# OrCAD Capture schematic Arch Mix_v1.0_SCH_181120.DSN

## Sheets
1 05 MCU PinOut: size A3; rev: v1.0
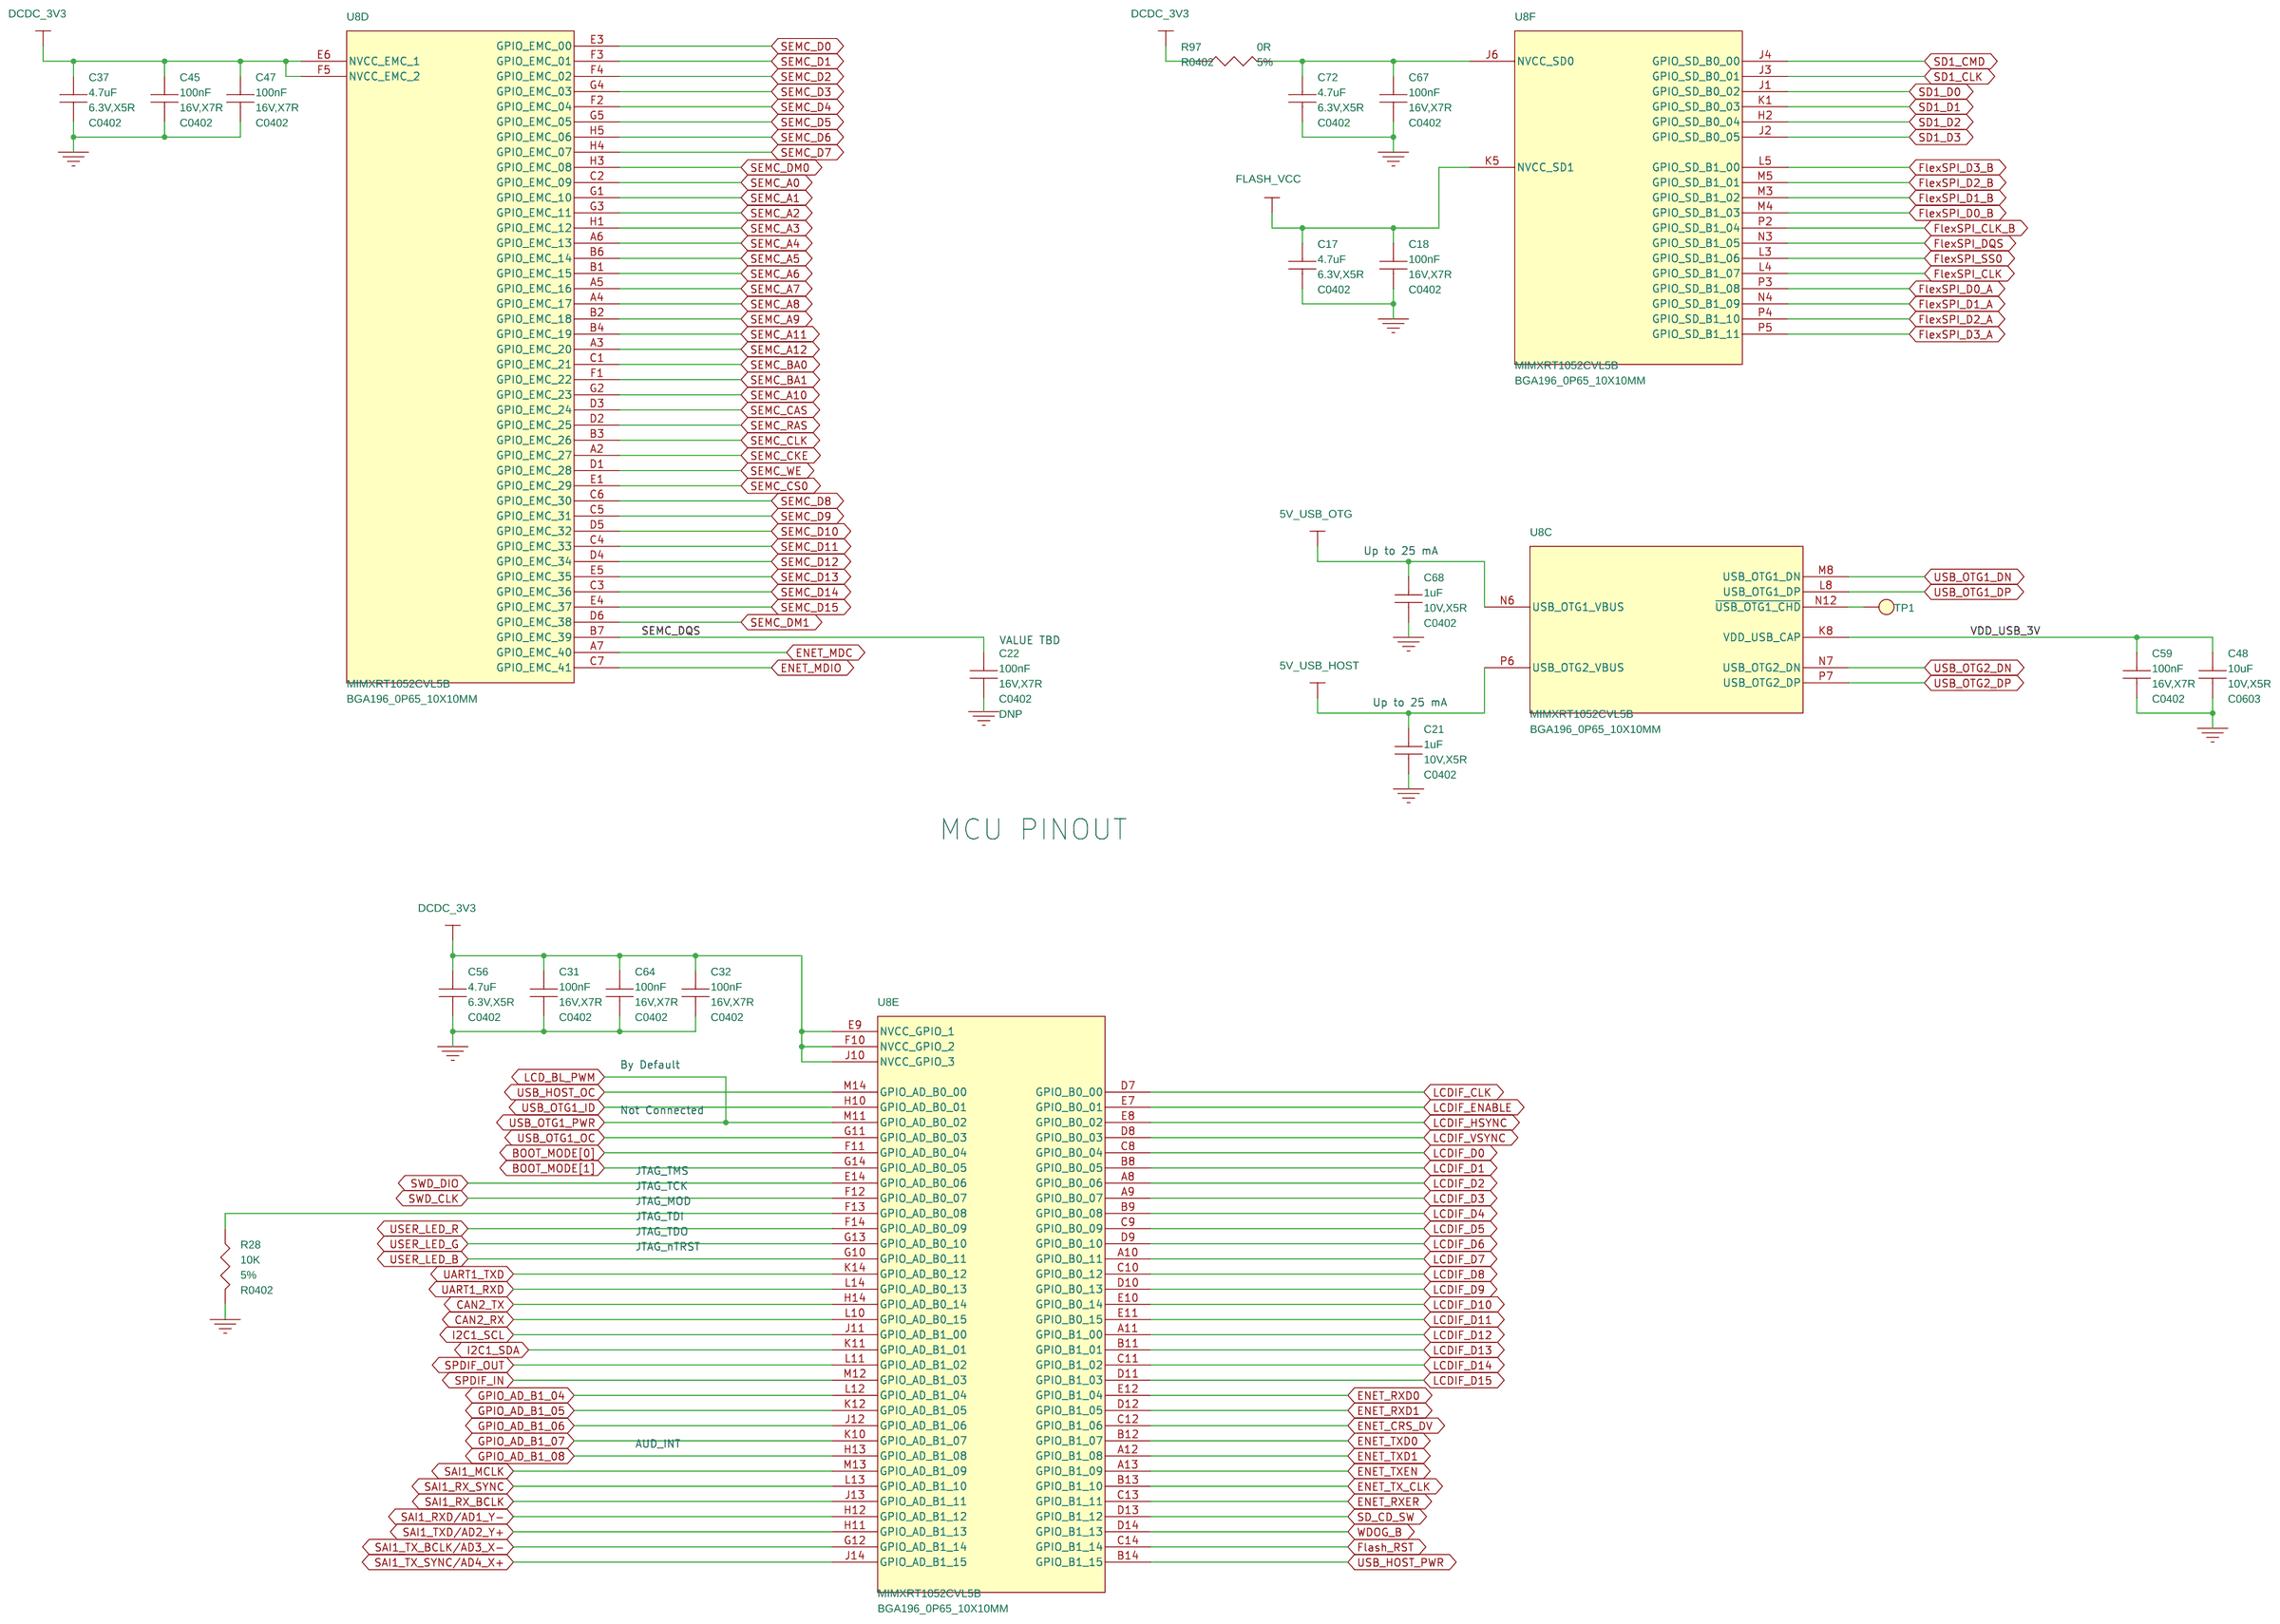
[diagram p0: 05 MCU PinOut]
2 03 Main Power: size A3
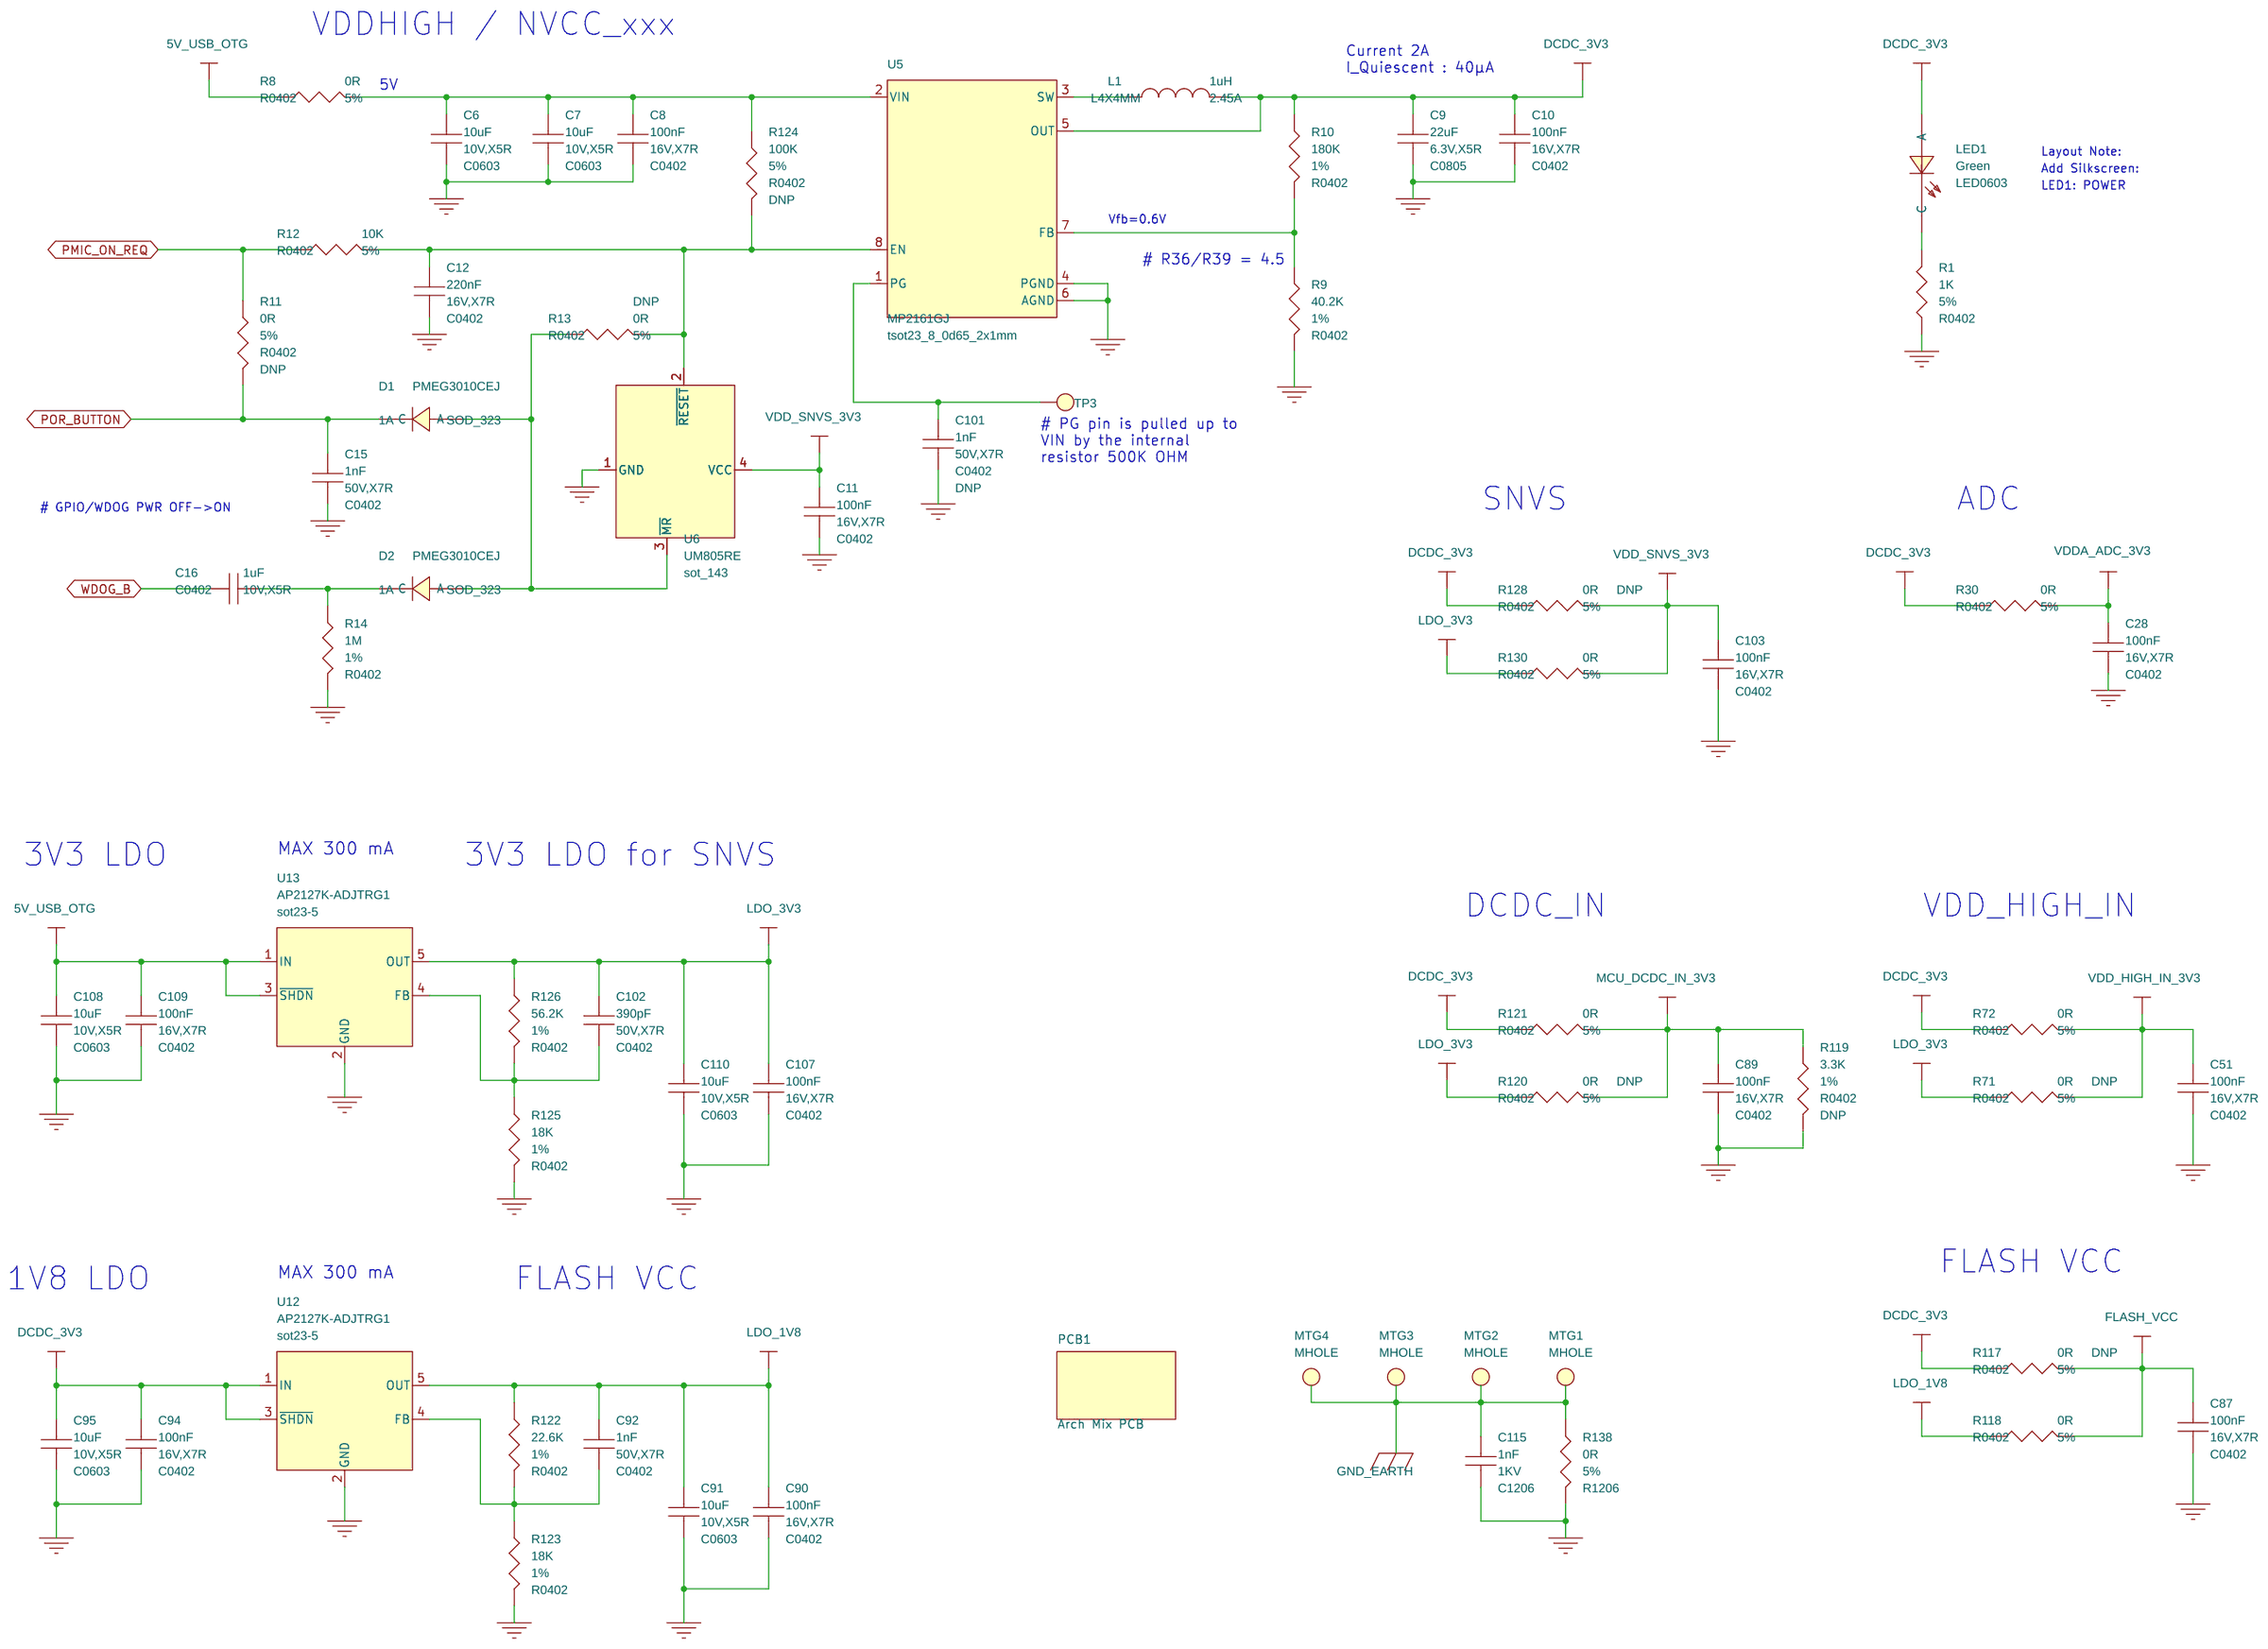
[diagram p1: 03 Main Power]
3 04 MCU Power: size A3
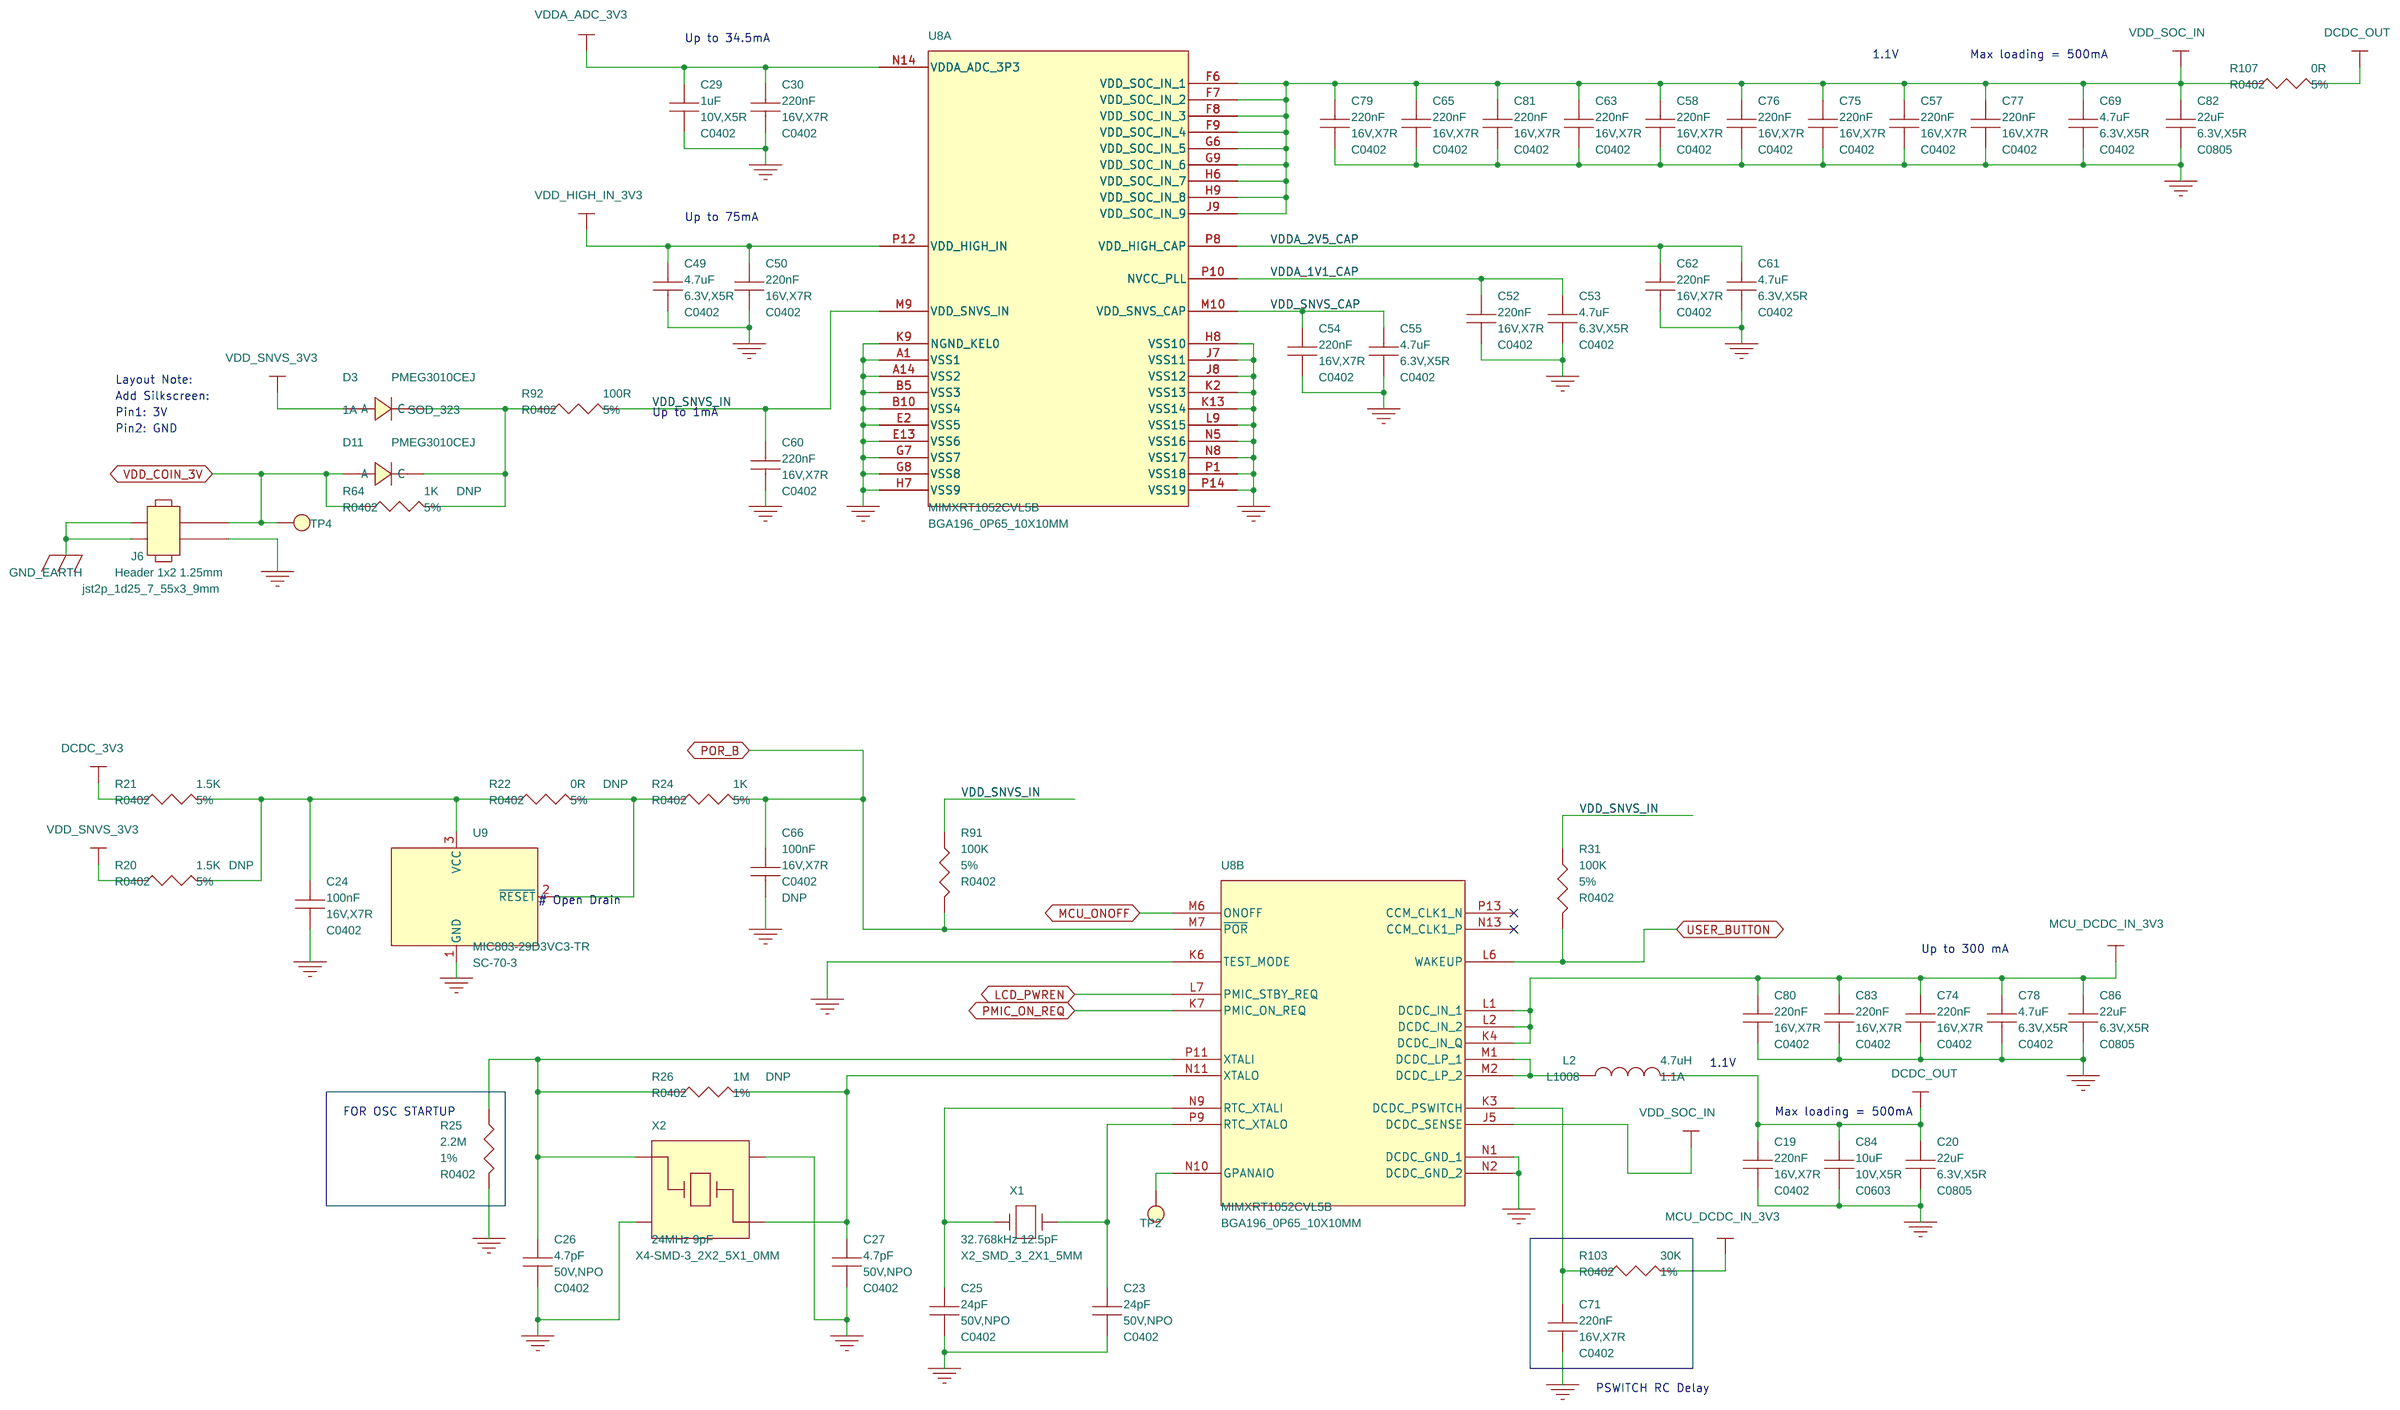
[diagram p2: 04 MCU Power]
4 02 Block Diagram
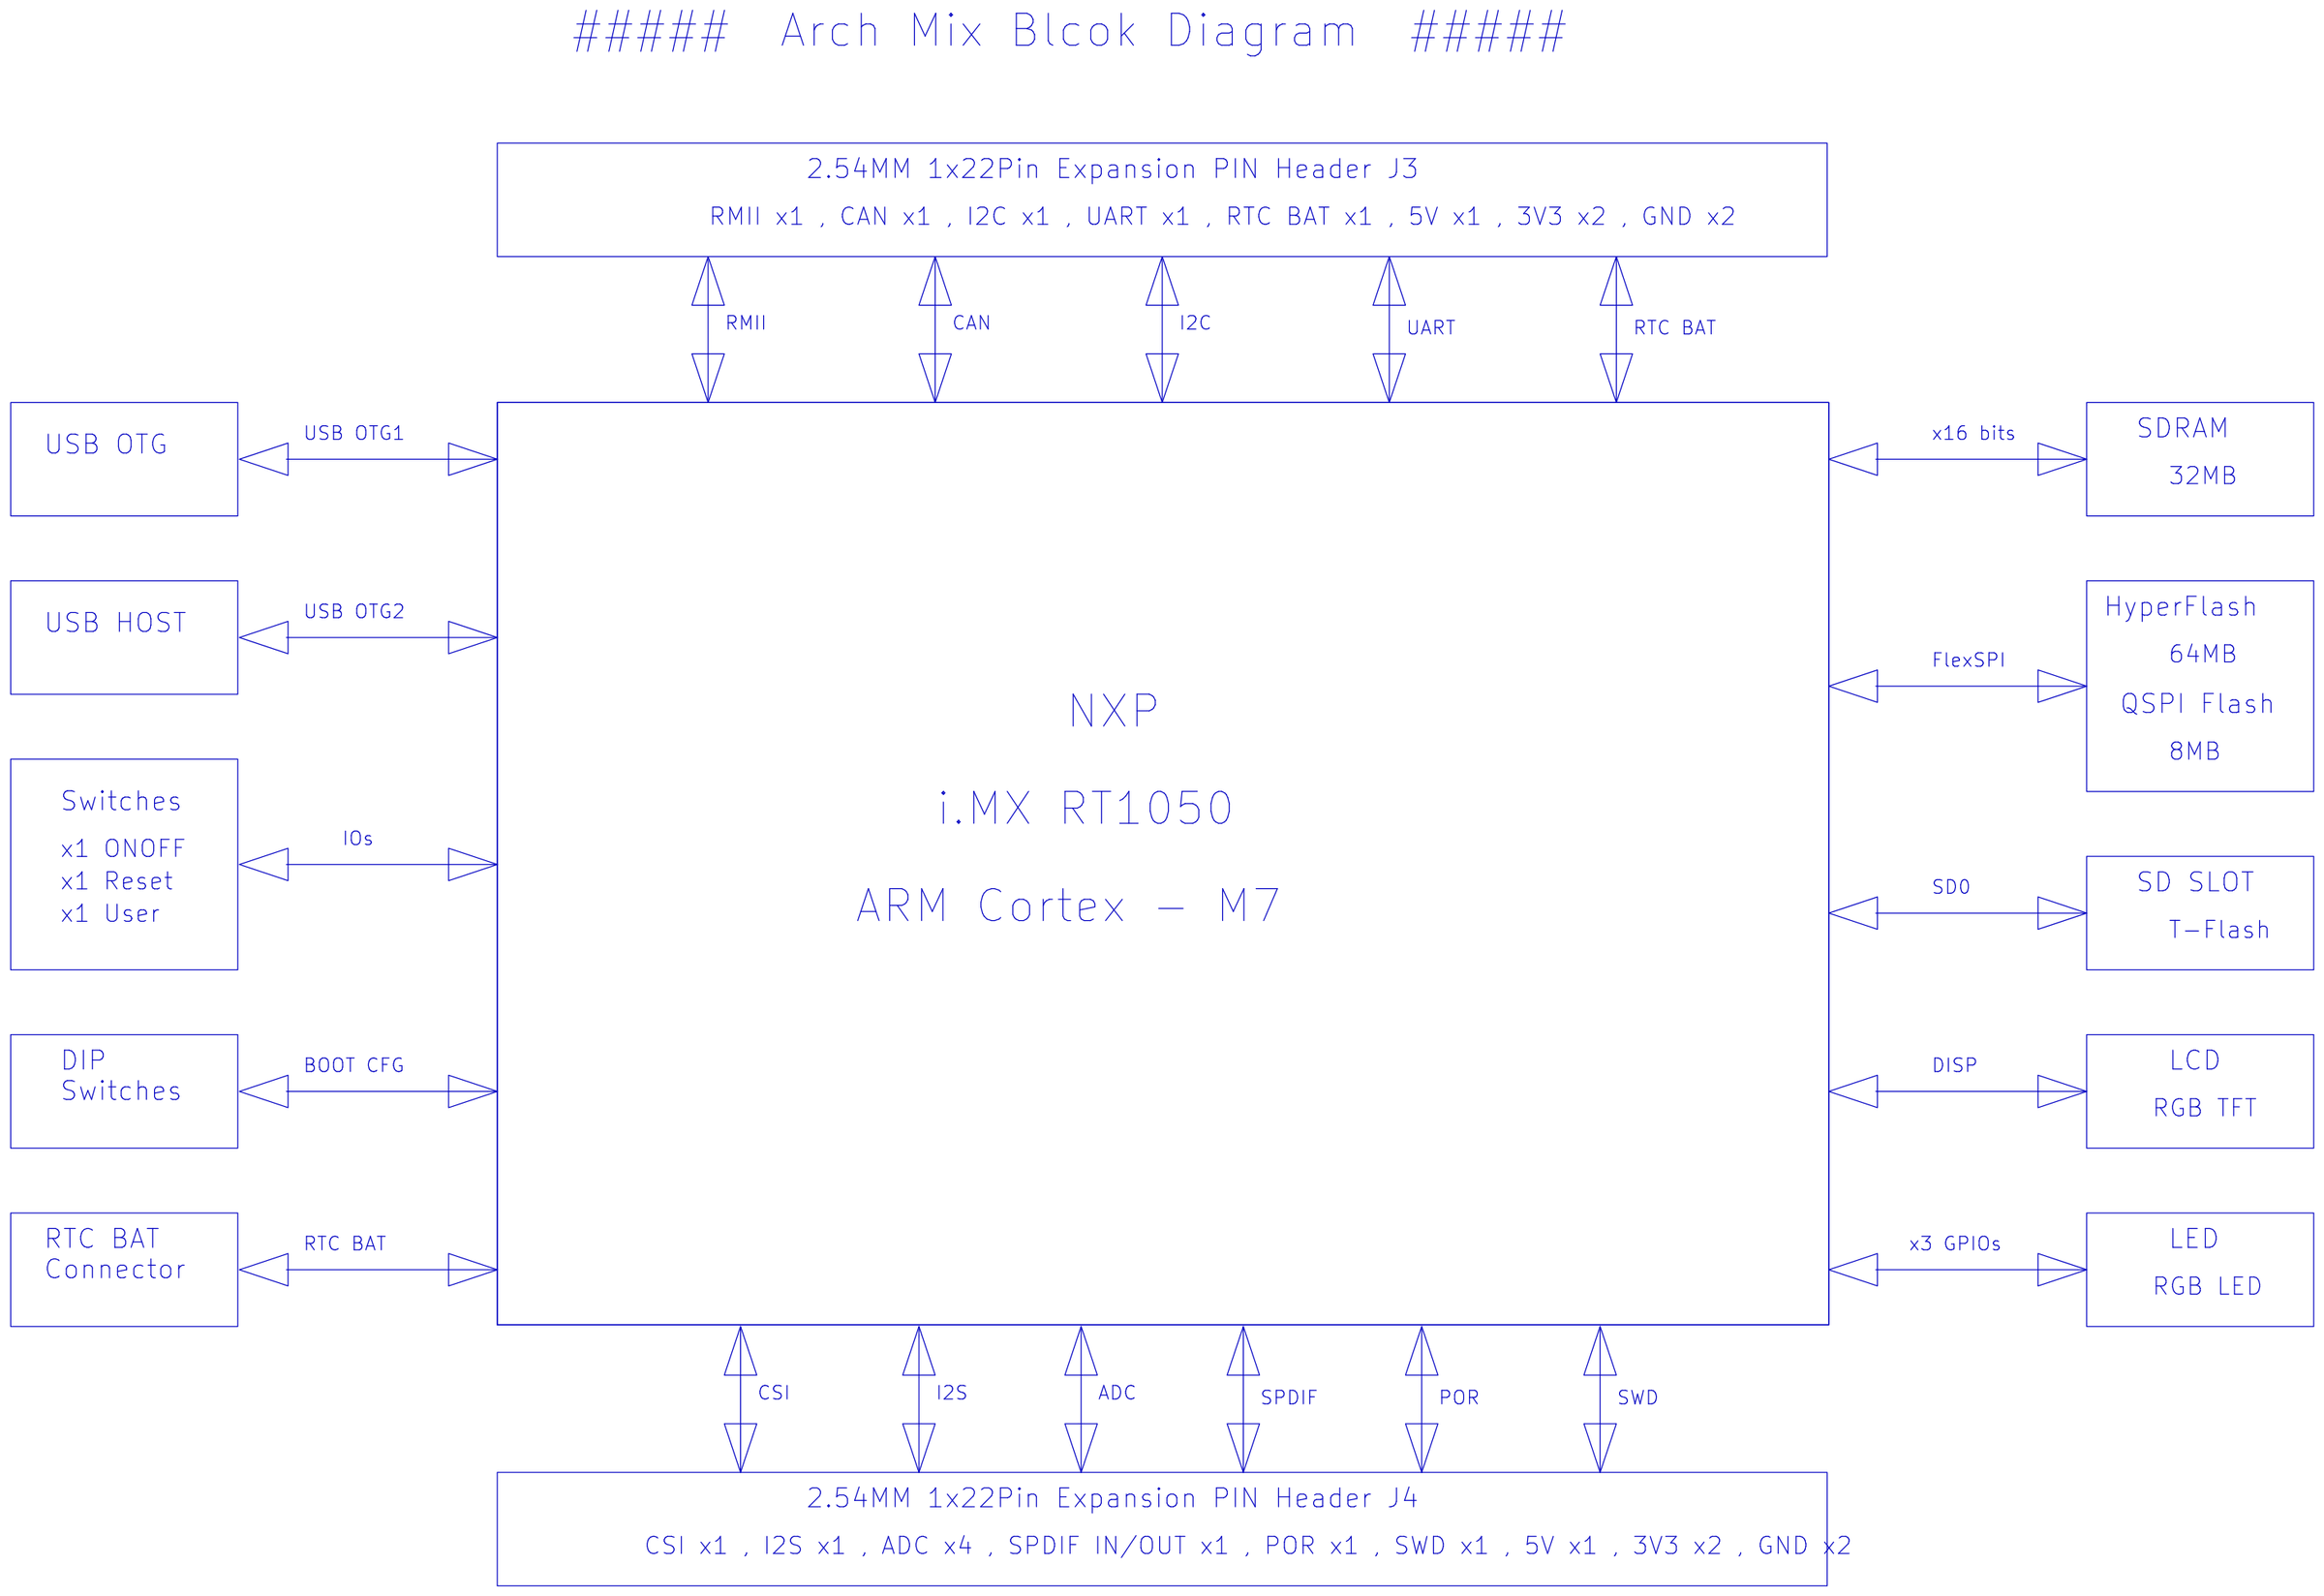
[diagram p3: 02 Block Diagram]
5 06 SDRAM / Flash / SD Card: size A3
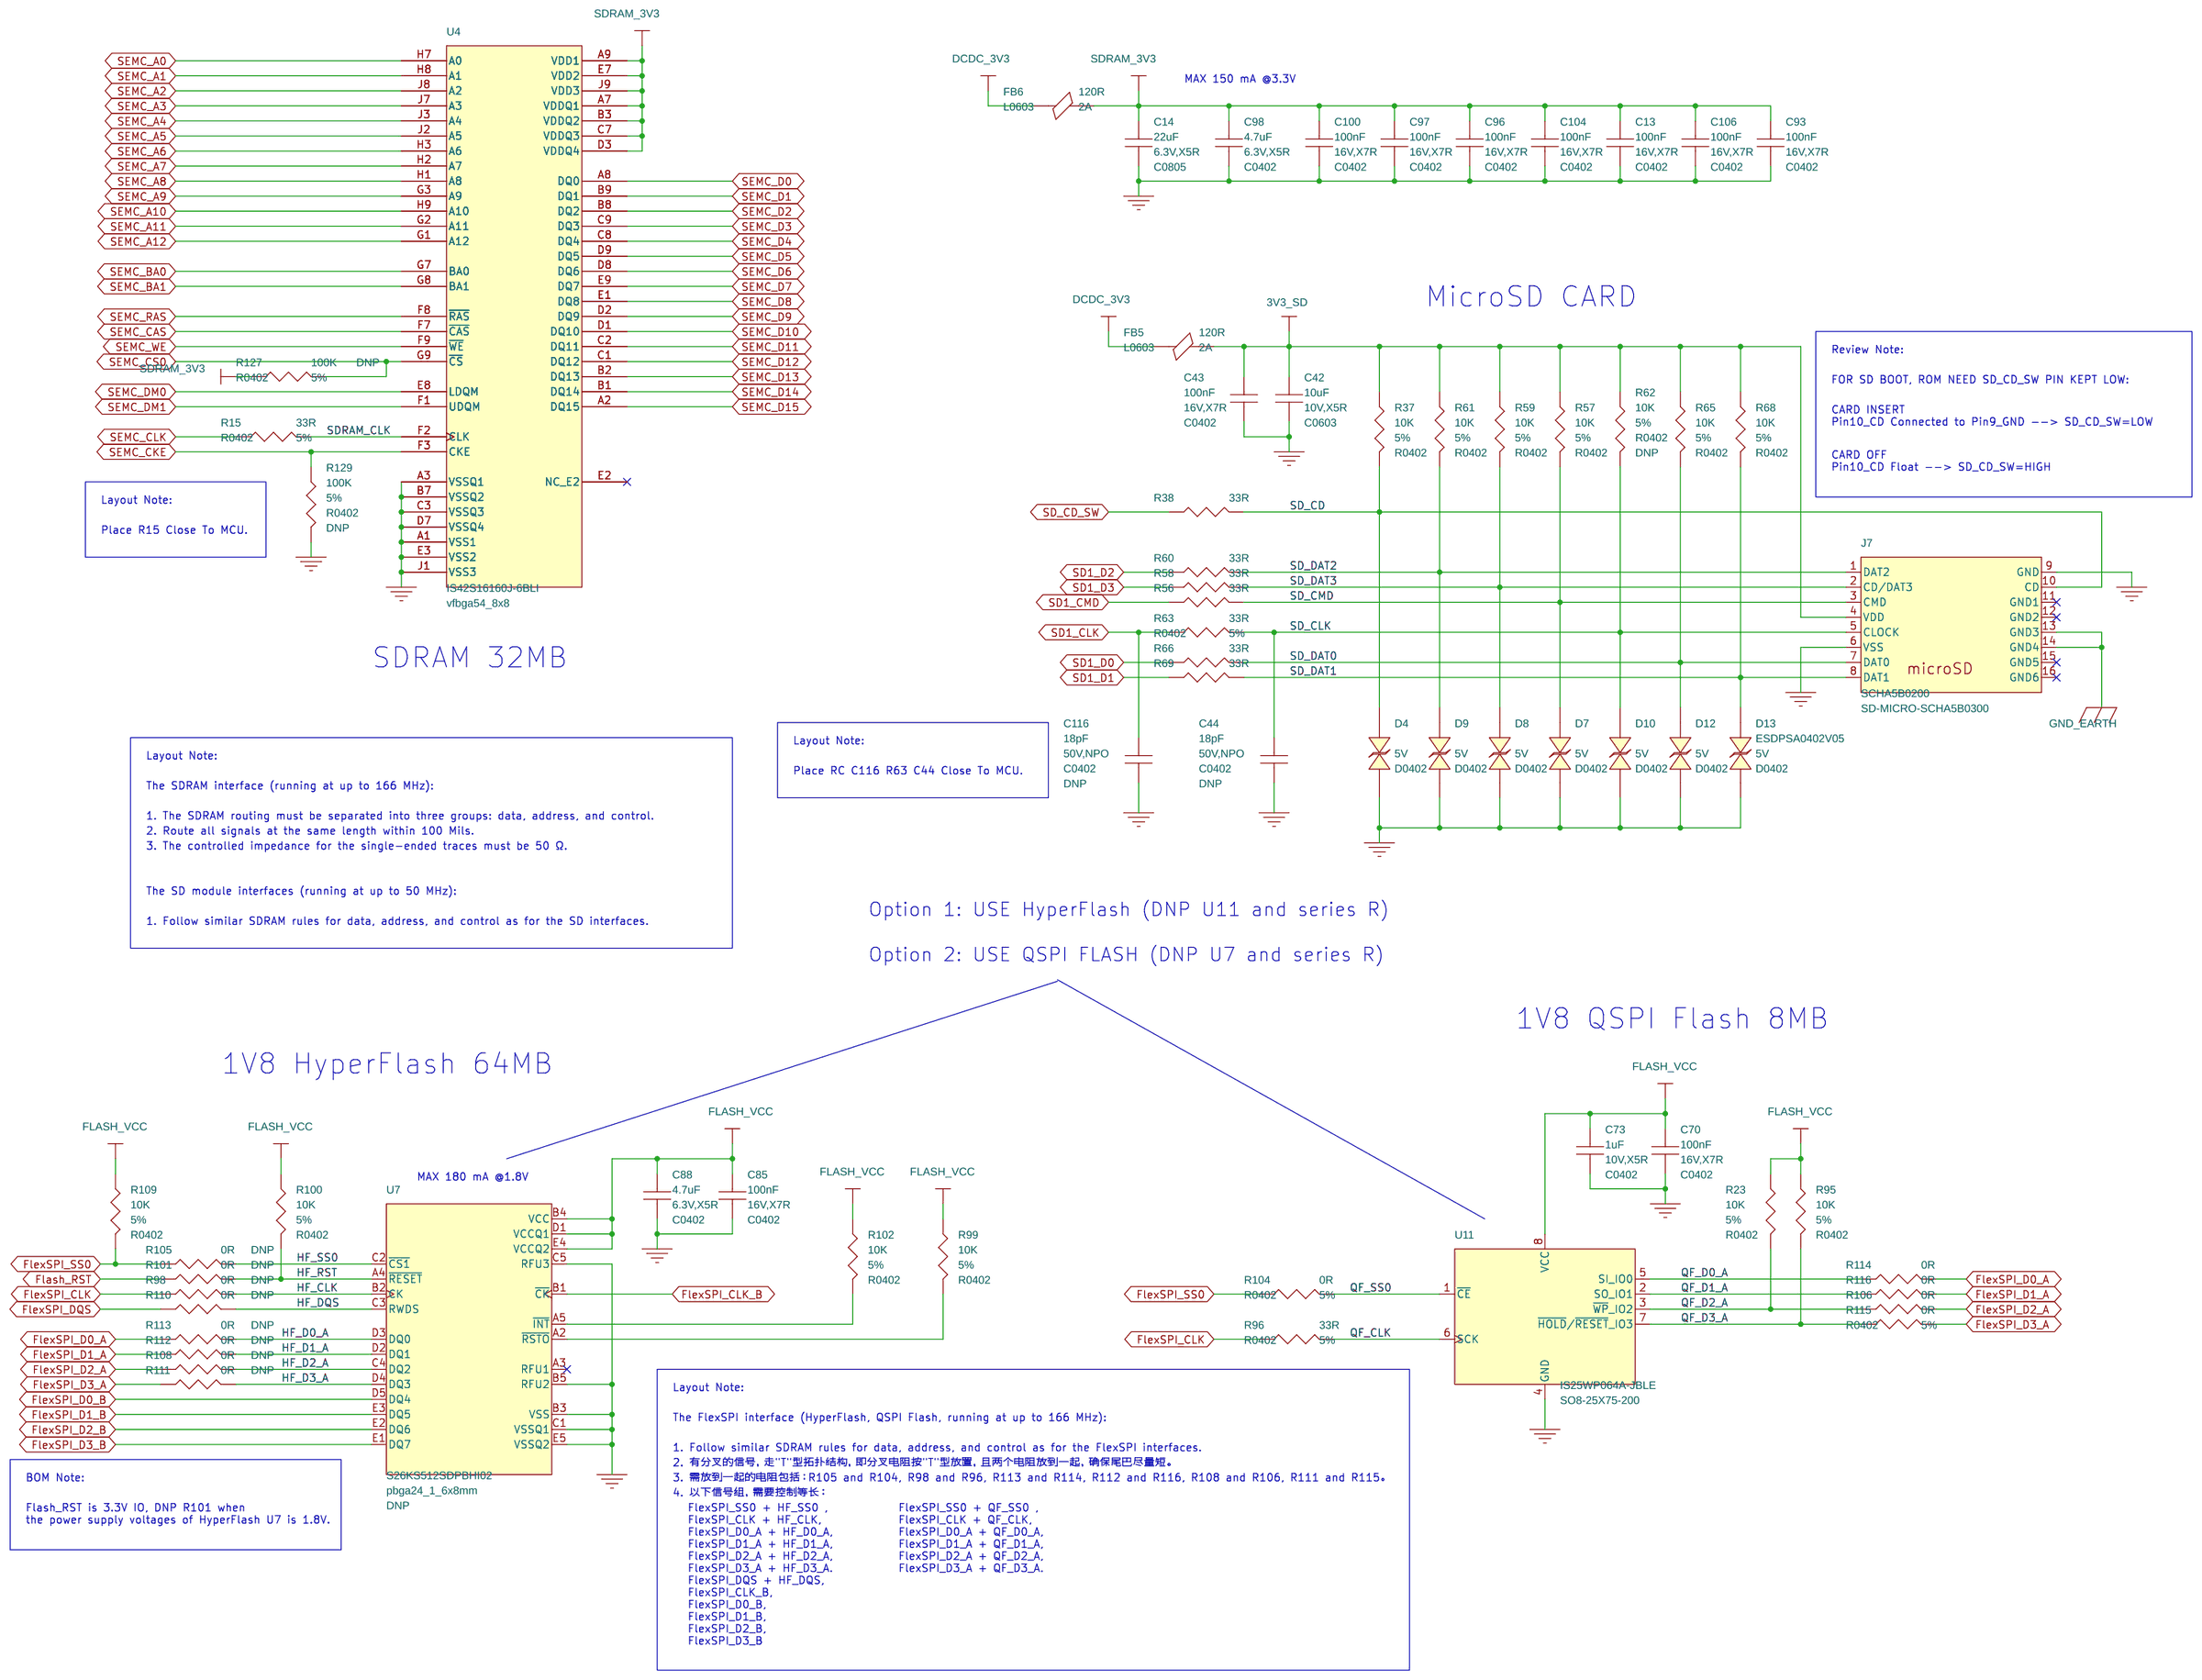
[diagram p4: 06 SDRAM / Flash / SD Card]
6 08 USB / EXP Headers: size A3
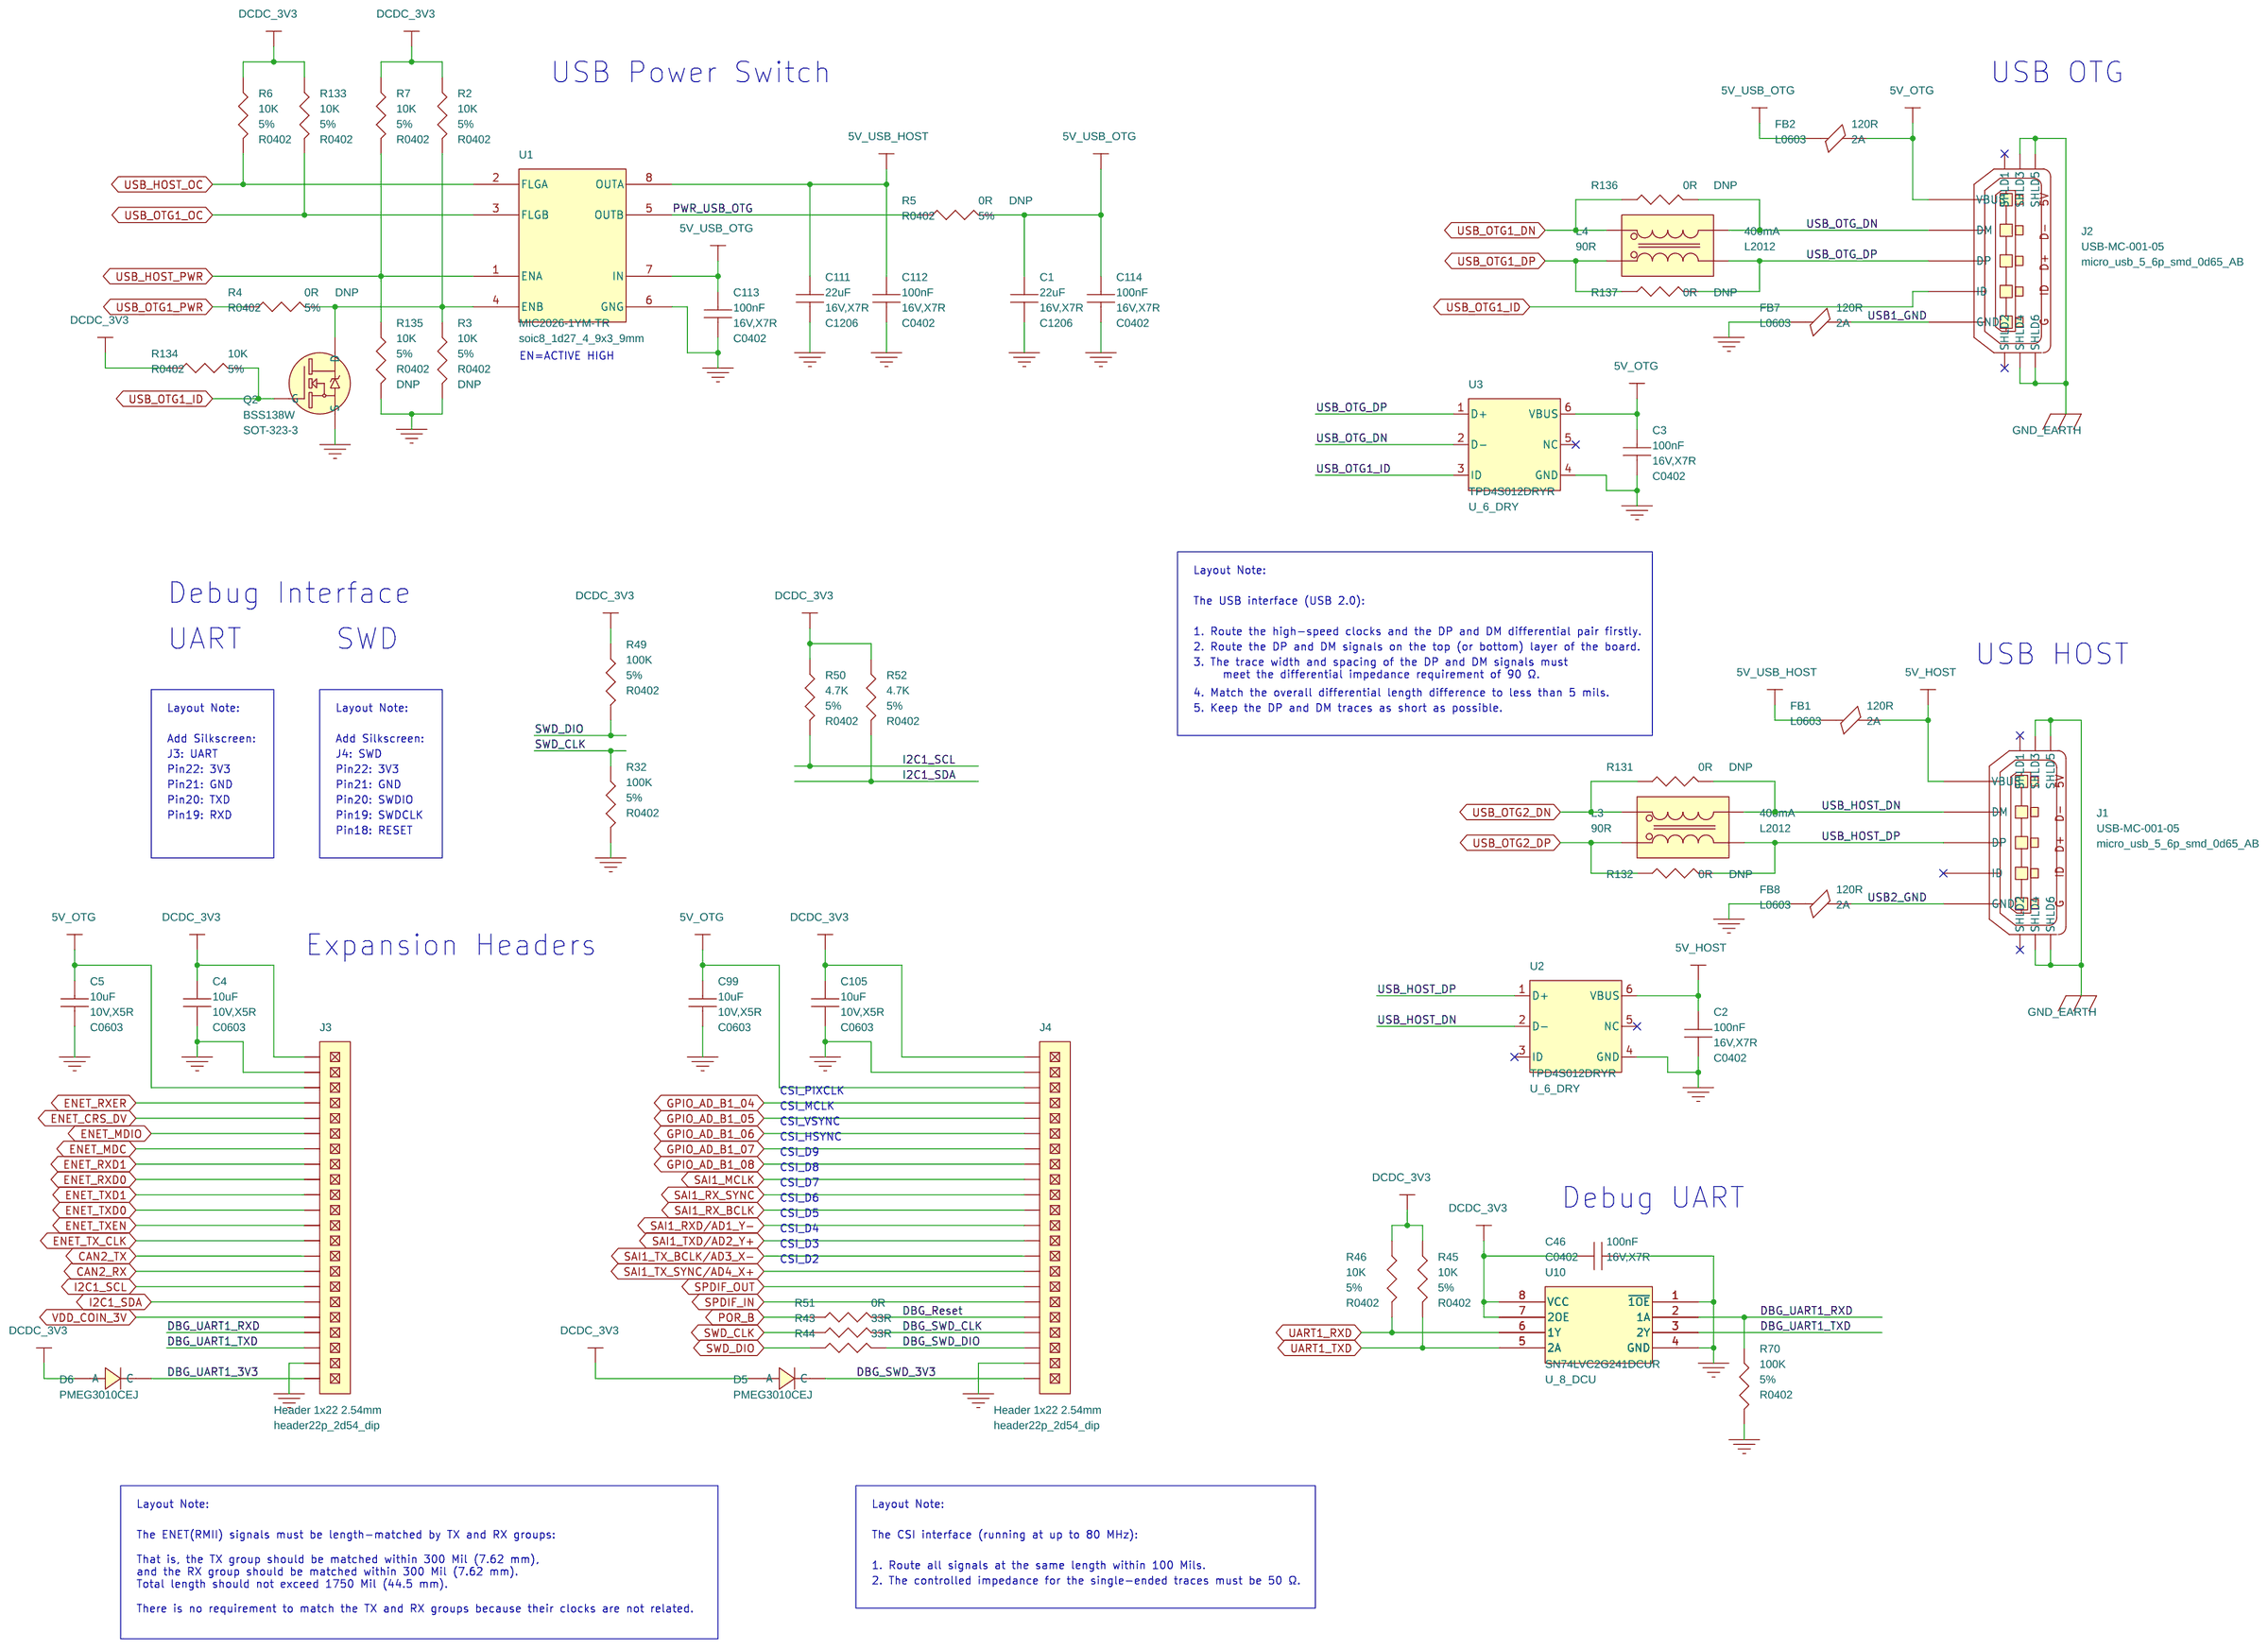
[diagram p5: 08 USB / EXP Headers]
7 01 Title / Revision History
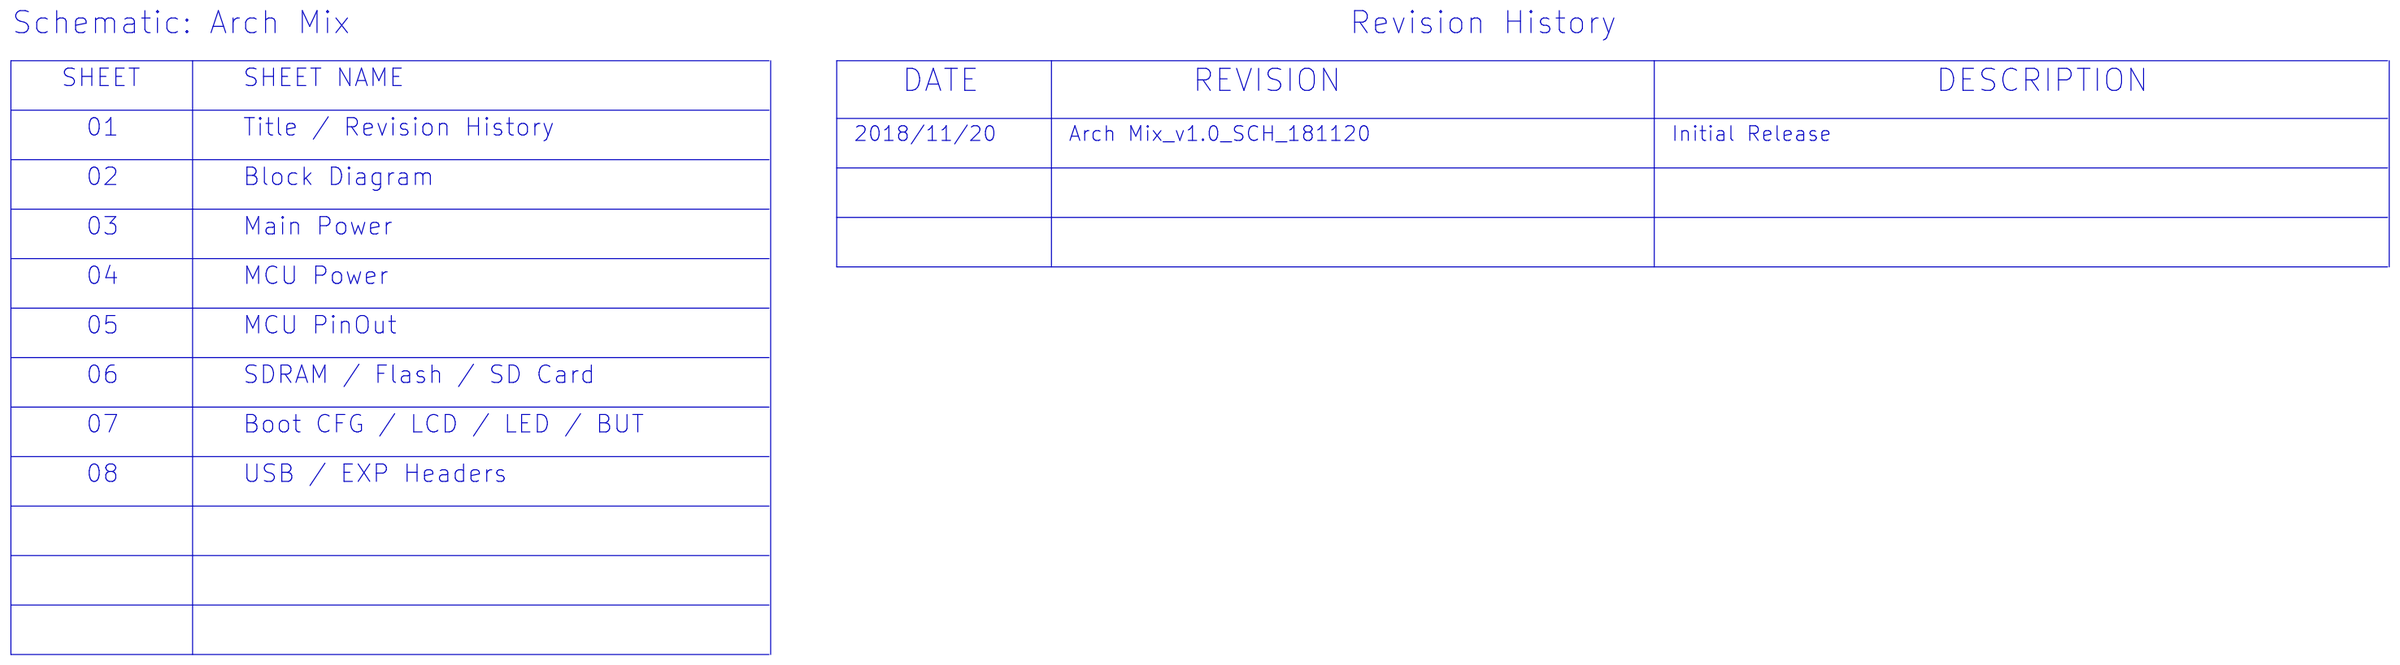
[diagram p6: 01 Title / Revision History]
8 07 Boot CFG / LCD / LED / BUT: size A3
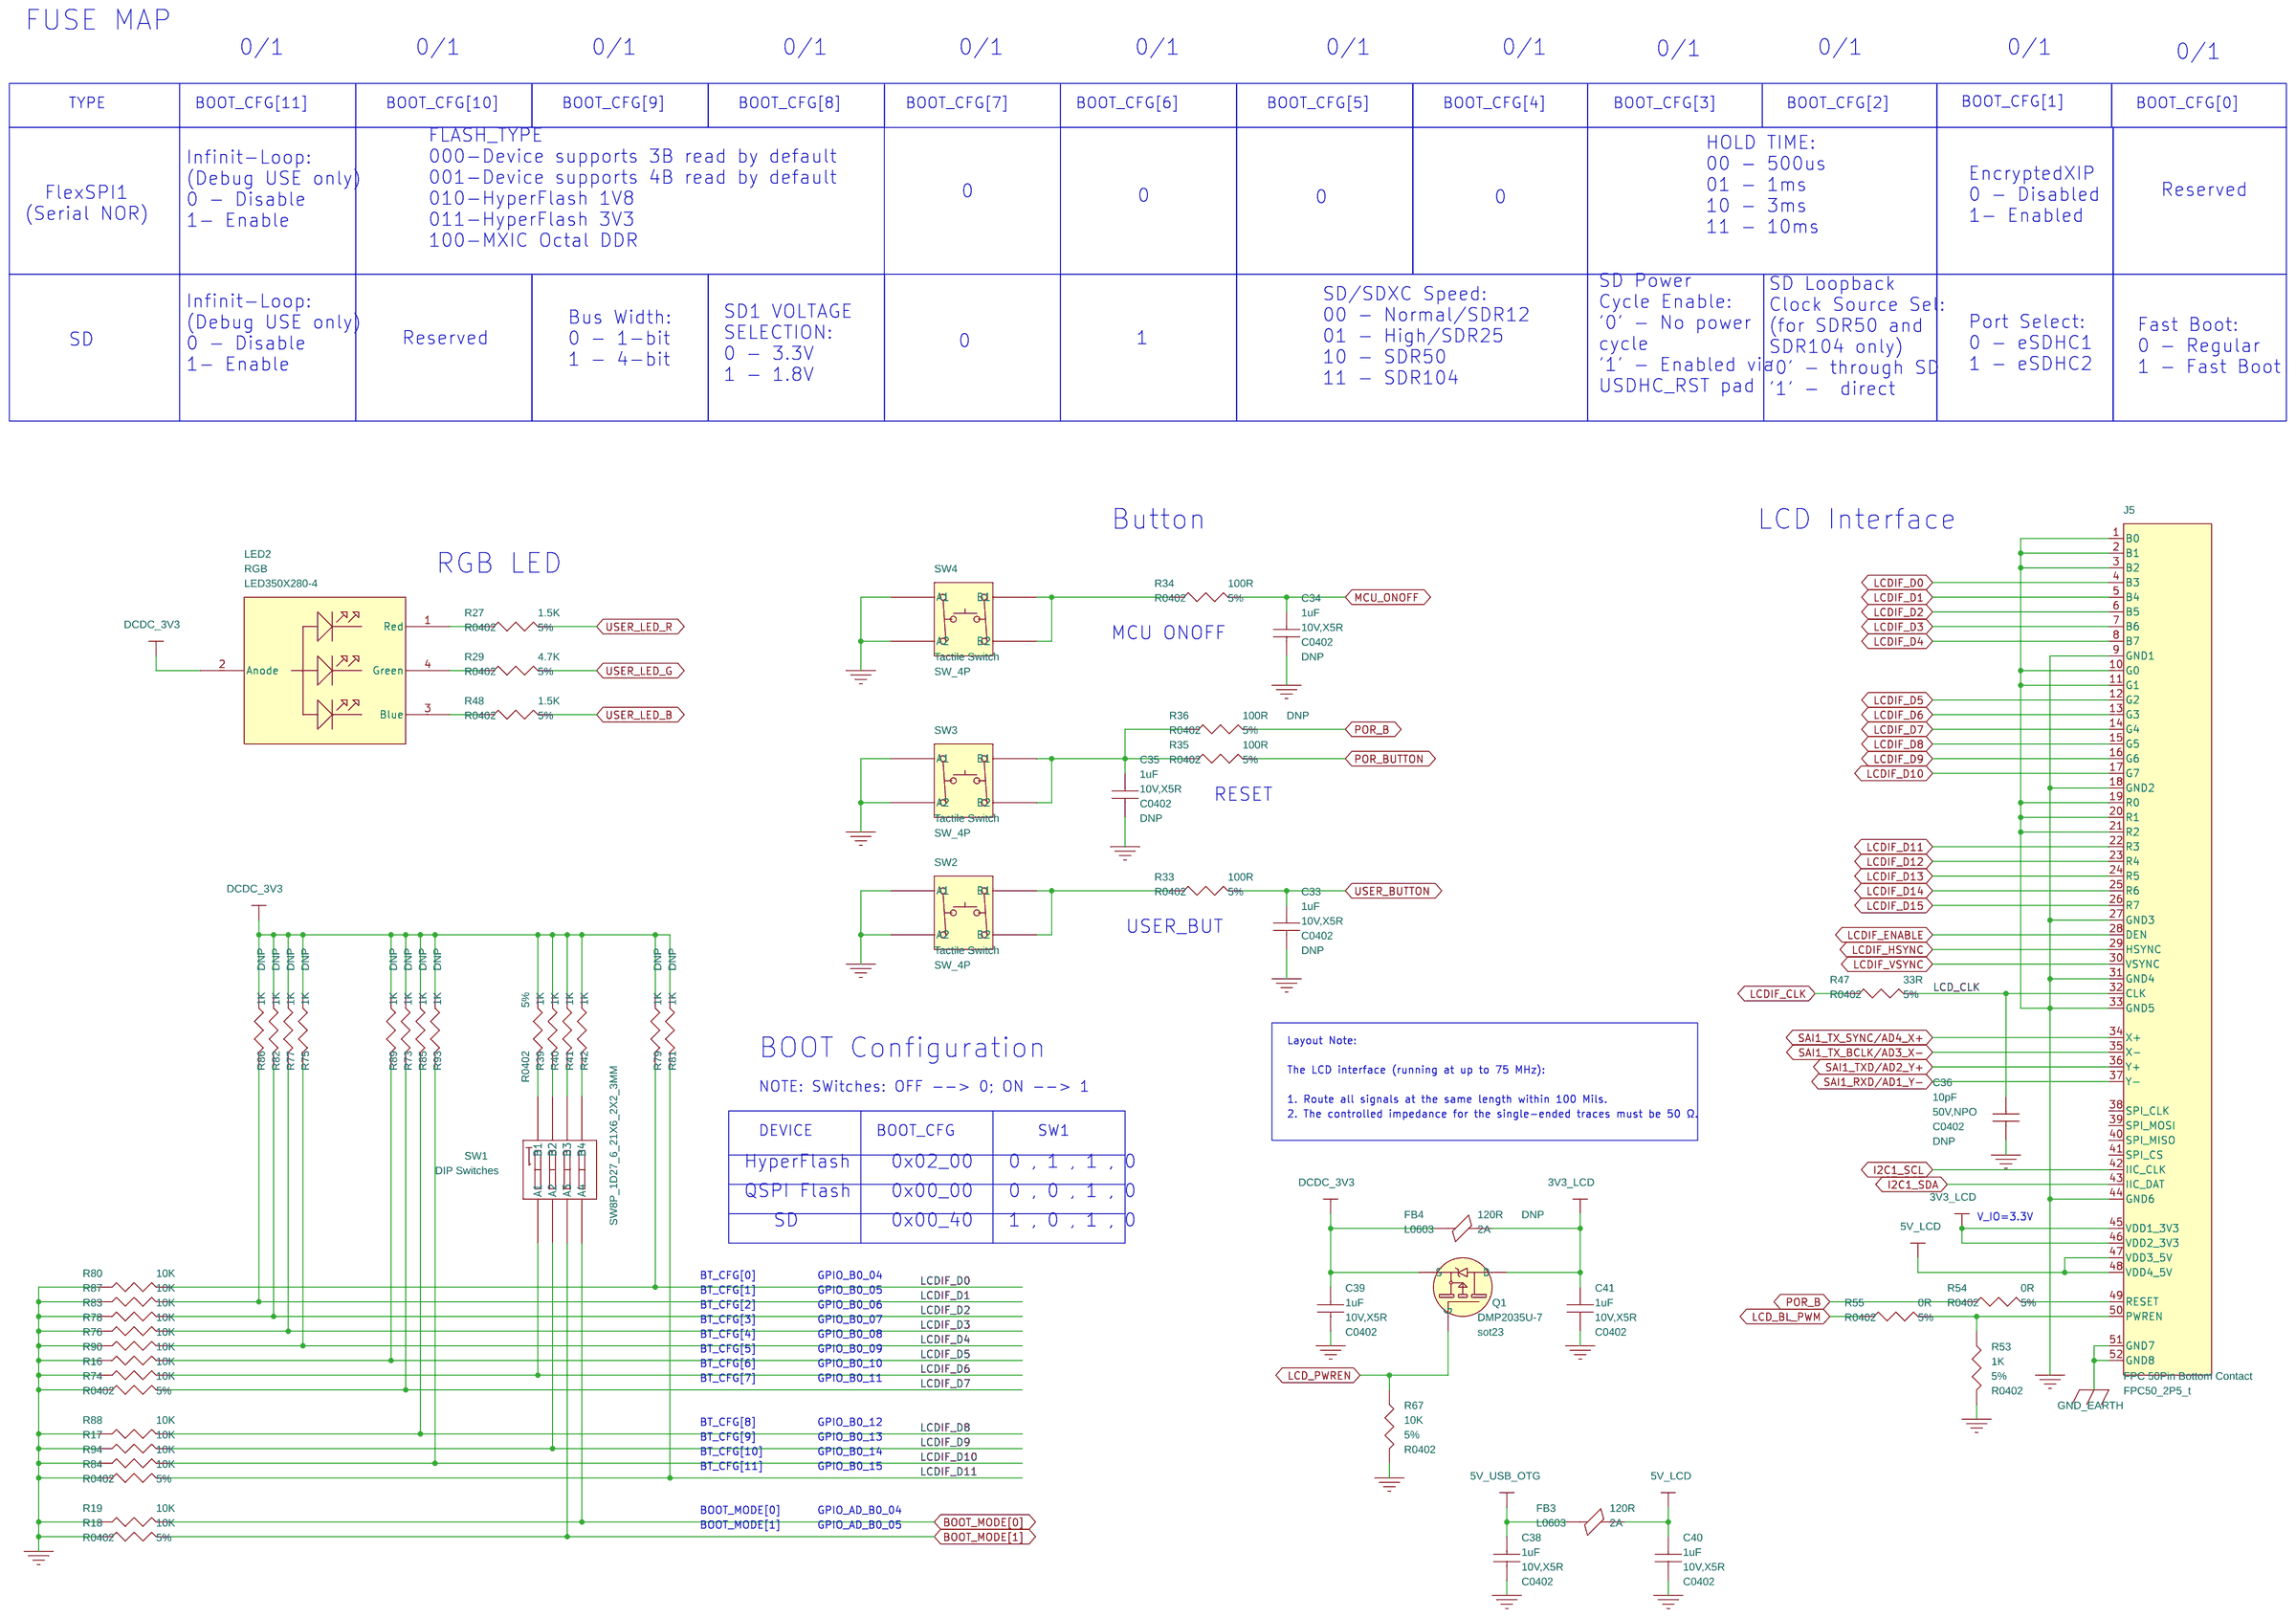
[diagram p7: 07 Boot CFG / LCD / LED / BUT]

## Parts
sheet 03 Main Power
C6  10uF  [C0603]
C7  10uF  [C0603]
C8  100nF  [C0402]
C9  22uF  [C0805]
C10  100nF  [C0402]
C11  100nF  [C0402]
C12  220nF  [C0402]
C15  1nF  [C0402]
C16  1uF  [C0402]
C28  100nF  [C0402]
C51  100nF  [C0402]
C87  100nF  [C0402]
C89  100nF  [C0402]
C90  100nF  [C0402]
C91  10uF  [C0603]
C92  1nF  [C0402]
C94  100nF  [C0402]
C95  10uF  [C0603]
C101  1nF  [C0402]
C102  390pF  [C0402]
C103  100nF  [C0402]
C107  100nF  [C0402]
C108  10uF  [C0603]
C109  100nF  [C0402]
C110  10uF  [C0603]
C115  1nF  [C1206]
D1  PMEG3010CEJ  [SOD_323]
D2  PMEG3010CEJ  [SOD_323]
L1  1uH  [L4X4MM]
LED1  Green  [LED0603]
MTG1  MHOLE  [mtgh160c80d_pl]
MTG2  MHOLE  [mtgh160c80d_pl]
MTG3  MHOLE  [mtgh160c80d_pl]
MTG4  MHOLE  [mtgh160c80d_pl]
PCB1  Arch Mix PCB  [NA]
R1  1K  [R0402]
R8  0R  [R0402]
R9  40.2K  [R0402]
R10  180K  [R0402]
R11  0R  [R0402]
R12  10K  [R0402]
R13  0R  [R0402]
R14  1M  [R0402]
R30  0R  [R0402]
R71  0R  [R0402]
R72  0R  [R0402]
R117  0R  [R0402]
R118  0R  [R0402]
R119  3.3K  [R0402]
R120  0R  [R0402]
R121  0R  [R0402]
R122  22.6K  [R0402]
R123  18K  [R0402]
R124  100K  [R0402]
R125  18K  [R0402]
R126  56.2K  [R0402]
R128  0R  [R0402]
R130  0R  [R0402]
R138  0R  [R1206]
TP3  TP_30MIL  [testpoint_30]
U5  MP2161GJ  [tsot23_8_0d65_2x1mm]
U6  UM805RE  [sot_143]
U12  AP2127K-ADJTRG1  [sot23-5]
U13  AP2127K-ADJTRG1  [sot23-5]
sheet 04 MCU Power
C19  220nF  [C0402]
C20  22uF  [C0805]
C23  24pF  [C0402]
C24  100nF  [C0402]
C25  24pF  [C0402]
C26  4.7pF  [C0402]
C27  4.7pF  [C0402]
C29  1uF  [C0402]
C30  220nF  [C0402]
C49  4.7uF  [C0402]
C50  220nF  [C0402]
C52  220nF  [C0402]
C53  4.7uF  [C0402]
C54  220nF  [C0402]
C55  4.7uF  [C0402]
C57  220nF  [C0402]
C58  220nF  [C0402]
C60  220nF  [C0402]
C61  4.7uF  [C0402]
C62  220nF  [C0402]
C63  220nF  [C0402]
C65  220nF  [C0402]
C66  100nF  [C0402]
C69  4.7uF  [C0402]
C71  220nF  [C0402]
C74  220nF  [C0402]
C75  220nF  [C0402]
C76  220nF  [C0402]
C77  220nF  [C0402]
C78  4.7uF  [C0402]
C79  220nF  [C0402]
C80  220nF  [C0402]
C81  220nF  [C0402]
C82  22uF  [C0805]
C83  220nF  [C0402]
C84  10uF  [C0603]
C86  22uF  [C0805]
D3  PMEG3010CEJ  [SOD_323]
D11  PMEG3010CEJ  [SOD_323]
J6  Header 1x2 1.25mm  [jst2p_1d25_7_55x3_9mm]
L2  4.7uH  [L1008]
R20  1.5K  [R0402]
R21  1.5K  [R0402]
R22  0R  [R0402]
R24  1K  [R0402]
R25  2.2M  [R0402]
R26  1M  [R0402]
R31  100K  [R0402]
R64  1K  [R0402]
R91  100K  [R0402]
R92  100R  [R0402]
R103  30K  [R0402]
R107  0R  [R0402]
TP2  TP_30MIL  [testpoint_30]
TP4  TP_40MIL  [TP40C_SMD]
U8  MIMXRT1052CVL5B  [BGA196_0P65_10X10MM]  (sections A,B,C,D,E,F)
U9  MIC803-29D3VC3-TR  [SC-70-3]
X1  32.768kHz 12.5pF  [X2_SMD_3_2X1_5MM]
X2  24MHz 9pF  [X4-SMD-3_2X2_5X1_0MM]
sheet 05 MCU PinOut
C17  4.7uF  [C0402]
C18  100nF  [C0402]
C21  1uF  [C0402]
C22  100nF  [C0402]
C31  100nF  [C0402]
C32  100nF  [C0402]
C37  4.7uF  [C0402]
C45  100nF  [C0402]
C47  100nF  [C0402]
C48  10uF  [C0603]
C56  4.7uF  [C0402]
C59  100nF  [C0402]
C64  100nF  [C0402]
C67  100nF  [C0402]
C68  1uF  [C0402]
C72  4.7uF  [C0402]
R28  10K  [R0402]
R97  0R  [R0402]
TP1  TP_30MIL  [testpoint_30]
sheet 06 SDRAM / Flash / SD Card
C13  100nF  [C0402]
C14  22uF  [C0805]
C42  10uF  [C0603]
C43  100nF  [C0402]
C44  18pF  [C0402]
C70  100nF  [C0402]
C73  1uF  [C0402]
C85  100nF  [C0402]
C88  4.7uF  [C0402]
C93  100nF  [C0402]
C96  100nF  [C0402]
C97  100nF  [C0402]
C98  4.7uF  [C0402]
C100  100nF  [C0402]
C104  100nF  [C0402]
C106  100nF  [C0402]
C116  18pF  [C0402]
D4  ESDPSA0402V05  [D0402]
D7  ESDPSA0402V05  [D0402]
D8  ESDPSA0402V05  [D0402]
D9  ESDPSA0402V05  [D0402]
D10  ESDPSA0402V05  [D0402]
D12  ESDPSA0402V05  [D0402]
D13  ESDPSA0402V05  [D0402]
FB5  120R  [L0603]
FB6  120R  [L0603]
J7  SCHA5B0200  [SD-MICRO-SCHA5B0300]
R15  33R  [R0402]
R23  10K  [R0402]
R37  10K  [R0402]
R38  33R  [R0402]
R56  33R  [R0402]
R57  10K  [R0402]
R58  33R  [R0402]
R59  10K  [R0402]
R60  33R  [R0402]
R61  10K  [R0402]
R62  10K  [R0402]
R63  33R  [R0402]
R65  10K  [R0402]
R66  33R  [R0402]
R68  10K  [R0402]
R69  33R  [R0402]
R95  10K  [R0402]
R96  33R  [R0402]
R98  0R  [R0402]
R99  10K  [R0402]
R100  10K  [R0402]
R101  0R  [R0402]
R102  10K  [R0402]
R104  0R  [R0402]
R105  0R  [R0402]
R106  0R  [R0402]
R108  0R  [R0402]
R109  10K  [R0402]
R110  0R  [R0402]
R111  0R  [R0402]
R112  0R  [R0402]
R113  0R  [R0402]
R114  0R  [R0402]
R115  0R  [R0402]
R116  0R  [R0402]
R127  100K  [R0402]
R129  100K  [R0402]
U4  IS42S16160J-6BLI  [vfbga54_8x8]
U7  S26KS512SDPBHI02  [pbga24_1_6x8mm]
U11  IS25WP064A-JBLE  [SO8-25X75-200]
sheet 07 Boot CFG / LCD / LED / BUT
C33  1uF  [C0402]
C34  1uF  [C0402]
C35  1uF  [C0402]
C36  10pF  [C0402]
C38  1uF  [C0402]
C39  1uF  [C0402]
C40  1uF  [C0402]
C41  1uF  [C0402]
FB3  120R  [L0603]
FB4  120R  [L0603]
J5  FPC 50Pin Bottom Contact  [FPC50_2P5_t]
LED2  RGB  [LED350X280-4]
Q1  DMP2035U-7  [sot23]
R16  10K  [R0402]
R17  10K  [R0402]
R18  10K  [R0402]
R19  10K  [R0402]
R27  1.5K  [R0402]
R29  4.7K  [R0402]
R33  100R  [R0402]
R34  100R  [R0402]
R35  100R  [R0402]
R36  100R  [R0402]
R39  1K  [R0402]
R40  1K  [R0402]
R41  1K  [R0402]
R42  1K  [R0402]
R47  33R  [R0402]
R48  1.5K  [R0402]
R53  1K  [R0402]
R54  0R  [R0402]
R55  0R  [R0402]
R67  10K  [R0402]
R73  1K  [R0402]
R74  10K  [R0402]
R75  1K  [R0402]
R76  10K  [R0402]
R77  1K  [R0402]
R78  10K  [R0402]
R79  1K  [R0402]
R80  10K  [R0402]
R81  1K  [R0402]
R82  1K  [R0402]
R83  10K  [R0402]
R84  10K  [R0402]
R85  1K  [R0402]
R86  1K  [R0402]
R87  10K  [R0402]
R88  10K  [R0402]
R89  1K  [R0402]
R90  10K  [R0402]
R93  1K  [R0402]
R94  10K  [R0402]
SW1  DIP Switches  [SW8P_1D27_6_21X6_2X2_3MM]
SW2  Tactile Switch  [SW_4P]
SW3  Tactile Switch  [SW_4P]
SW4  Tactile Switch  [SW_4P]
sheet 08 USB / EXP Headers
C1  22uF  [C1206]
C2  100nF  [C0402]
C3  100nF  [C0402]
C4  10uF  [C0603]
C5  10uF  [C0603]
C46  100nF  [C0402]
C99  10uF  [C0603]
C105  10uF  [C0603]
C111  22uF  [C1206]
C112  100nF  [C0402]
C113  100nF  [C0402]
C114  100nF  [C0402]
D5  PMEG3010CEJ  [SOD_323]
D6  PMEG3010CEJ  [SOD_323]
FB1  120R  [L0603]
FB2  120R  [L0603]
FB7  120R  [L0603]
FB8  120R  [L0603]
J1  USB-MC-001-05  [micro_usb_5_6p_smd_0d65_AB]
J2  USB-MC-001-05  [micro_usb_5_6p_smd_0d65_AB]
J3  Header 1x22 2.54mm  [header22p_2d54_dip]
J4  Header 1x22 2.54mm  [header22p_2d54_dip]
L3  90R  [L2012]
L4  90R  [L2012]
Q2  BSS138W  [SOT-323-3]
R2  10K  [R0402]
R3  10K  [R0402]
R4  0R  [R0402]
R5  0R  [R0402]
R6  10K  [R0402]
R7  10K  [R0402]
R32  100K  [R0402]
R43  33R  [R0402]
R44  33R  [R0402]
R45  10K  [R0402]
R46  10K  [R0402]
R49  100K  [R0402]
R50  4.7K  [R0402]
R51  0R  [R0402]
R52  4.7K  [R0402]
R70  100K  [R0402]
R131  0R  [R0402]
R132  0R  [R0402]
R133  10K  [R0402]
R134  10K  [R0402]
R135  10K  [R0402]
R136  0R  [R0402]
R137  0R  [R0402]
U1  MIC2026-1YM-TR  [soic8_1d27_4_9x3_9mm]
U2  TPD4S012DRYR  [U_6_DRY]
U3  TPD4S012DRYR  [U_6_DRY]
U10  SN74LVC2G241DCUR  [U_8_DCU]

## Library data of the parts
C4-C7 C42 C48 C84 C91 C95 C99 C105 C108 C110 = CC: SMD CAP Ceramic 10uF-10V-10%-X5R;0603; Manufacturer Part Number: YAGEO;CC0603KRX5R6BB106; PN: 302010103; Part Type: Ceramic; Rating: 10V,X5R; Status: BeagleBone Carrier Board
C2 C3 C8 C10 C11 C13 C18 C24 C28 C31 C32 C43 C45-C47 C51 C59 C64 C67 C70 C85 C87 C89 C90 C93 C94 C96 C97 C100 C103 C104 C106 C107 C109 C112-C114 = CC: SMD CAP Ceramic 100nF-16V-10%-X7R;0402; Manufacturer Part Number: YAGEO;CC0402KRX7R7BB104; PN: 302010004; Part Type: Ceramic; Rating: 16V,X7R; Status: BeagleBone Carrier Board
C9 C14 C20 C82 C86 = CC: SMD CAP Ceramic 22uF-6.3V-20%-X5R;0805; Manufacturer Part Number: YAGEO;CC0805MKX5R5BB226; PN: 302010171; Part Type: Ceramic; Rating: 6.3V,X5R; Status: RT-M7
C12 C19 C30 C50 C52 C54 C57 C58 C60 C62 C63 C65 C71 C74-C77 C79-C81 C83 = CC: SMD CAP Ceramic 220nF-16V-10%-X7R;0402; Manufacturer Part Number: Yageo;CC0402KRX7R7BB224; PN: 302010051; Part Type: Ceramic; Rating: 16V,X7R; Status: RT-M7
C15 C92 = CC: SMD CAP Ceramic 1nF-50V-10%-X7R;0402; Manufacturer Part Number: YAGEO;CC0402KRX7R9BB102; PN: 302010005; Part Type: Ceramic; Rating: 50V,X7R; Status: RT-M7
C16 C21 C29 C38-C41 C68 C73 = CC: SMD CAP Ceramic 1uF-10V-10%-X5R;0402; Manufacturer Part Number: YAGEO;CC0402KRX5R6BB105; PN: 302010040; Part Type: Ceramic; Rating: 10V,X5R; Status: BeagleBone Carrier Board
C101 = CC: SMD CAP Ceramic 1nF-50V-10%-X7R;0402; ASSY: DNP; Manufacturer Part Number: YAGEO;CC0402KRX7R9BB102; PN: 302010005; Part Type: Ceramic; Rating: 50V,X7R; Status: RT-M7
C102 = CC: SMD CAP Ceramic;390pF-50V-10%-X7R; Manufacturer Part Number: YAGEO;CC0402KRX7R9BB391; PN: 302010260; Part Type: Ceramic; Rating: 50V,X7R; Status: RT-M7
C115 = CC: SMD CAP Ceramic 1nF-1KV-10%-X7R;1206; Manufacturer Part Number: YAGEO;CC1206KKX7RCBB102; PN: 302010189; Part Type: Ceramic; Rating: 1KV; Status: BeagleBone Carrier Board
D1-D3 D5 D6 D11 = D: SMD Diode Schottky 30V-1A;SOD-323F; Manufacturer Part Number: NXP Semiconductors;PMEG3010CEJ,115; PN: 304020022; Part Type: Diode; Rating: 1A; Status: BeagleBone Carrier Board
L1 = L: SMD Inductor;1uH-30%-2.45A-4*4*1.8mm; Manufacturer Part Number: Murata;LQH44PN1R0NP0L; PN: 303010119; Part Type: Inductor; Rating: 2.45A; Status: RT-M7
LED1 = Single_LED: SMD LED Clear-Green;LED-0603; Manufacturer Part Number: Everlight;19-217/G7C-AN1P2/3T(正贴); PN: 304090043; Part Type: LED; Status: BeagleBone Carrier Board
MTG1-MTG4 = MHOLE
PCB1 = PCB: PCB;Arch Mix_v1.0-红油白字-6层; Manufacturer Part Number: 化学沉金-68*40*1.6mm-FR4; PN: 319013237
R1 R24 R39-R42 R53 = R: SMD RES 1K-5%-1/16W;0402; Manufacturer Part Number: YAGEO;RC0402JR-071KL; PN: 301010006; Part Type: RES; Rating: 5%; Status: BeagleBone Carrier Board
R8 R30 R51 R54 R55 R72 R97 R104 R106 R107 R114-R116 R118 R121 R130 = R: SMD RES 0R-5%-1/16W;0402; Manufacturer Part Number: YAGEO;RC0402JR-070RL; PN: 301010000; Part Type: RES; Rating: 5%; Status: BeagleBone Carrier Board
R9 = R: SMD RES 40.2K-1%-1/16W;0402; Manufacturer Part Number: YAGEO;RC0402FR-0740K2L; PN: 301010062; Part Type: RES; Rating: 1%; Status: RT-M7
R10 = R: SMD RES 180K-1%-1/16W;0402; PN: 301010814; Part Type: RES; Rating: 1%; Status: RT-M7
R5 R11 R13 R22 R71 R98 R101 R105 R108 R110-R113 R117 R120 R128 R131 R132 R136 R137 = R: SMD RES 0R-5%-1/16W;0402; ASSY: DNP; Manufacturer Part Number: YAGEO;RC0402JR-070RL; PN: 301010000; Part Type: RES; Rating: 5%; Status: BeagleBone Carrier Board
R2 R6 R7 R12 R16-R18 R23 R28 R37 R45 R46 R57 R59 R61 R65 R67 R68 R74 R78 R80 R83 R84 R87 R94 R95 R99 R100 R102 R109 R133 R134 = R: SMD RES 10K-5%-1/16W;0402; Manufacturer Part Number: YAGEO;RC0402JR-0710KL; PN: 301010004; Part Type: RES; Rating: 5%; Status: BeagleBone Carrier Board
R14 = R: SMD RES 1M-1%-1/16W;0402; Manufacturer Part Number: YAGEO;RC0402FR-071ML; PN: 301010043; Part Type: RES; Rating: 1%; Status: BeagleBone Carrier Board
R119 = R: SMD RES 3.3K-5%-1/16W;0402; ASSY: DNP; Manufacturer Part Number: YAGEO;RC0402JR-073K3L; PN: 301010035; Part Type: RES; Rating: 1%; Status: Not Used
R122 = R: SMD RES 22.6K-1%-1/10W;0402; Manufacturer Part Number: YAGEO;RC0402FR-0722K6L; PN: 301010807; Part Type: RES; Rating: 1%; Status: RT-M7
R123 R125 = R: SMD RES 18K-1%-1/16W;0402; Manufacturer Part Number: Yageo;RC0402FR-0718KL; PN: 301011349; Part Type: RES; Rating: 1%; Status: RT-M7
R124 R127 R129 = R: SMD RES 100K-5%-1/16W;0402; ASSY: DNP; Manufacturer Part Number: YAGEO;RC0402JR-07100KL; PN: 301010033; Part Type: RES; Rating: 5%; Status: BeagleBone Carrier Board
R126 = R: SMD RES 56.2K-1%-1/16W;0402; Manufacturer Part Number: YAGEO;RC0402FR-0756K2L; PN: 301010806; Part Type: RES; Rating: 1%; Status: RT-M7
R138 = R: SMD RES 0R-5%-1/4W;1206; Manufacturer Part Number: YAGEO;RC1206JR-070RL; PN: 301010407; Part Type: RES; Rating: 5%; Status: BeagleBone Carrier Board
TP1-TP3 = T_POINT_R: TEST POINT PAD .035 SMT, no part to order; AGILE_PN: 510-75618; CAD_APPROVED: Yes; HEIGHT: 0.1MM; ROHS: Yes
U5 = MP2161: SMD IC PMIC;DCDC Buck-ADJ-2A;TSOT23-8; Manufacturer Part Number: MPS;MP2161GJ; PN: 310031334; Part Type: DCDC; Status: RT-M7
U6 = UM805_4P: SMD IC PMIC;Reset Circuit;2.63V VTH RST;SOT143; Manufacturer Part Number: Union Semiconductor;UM805RE; PN: 310031538; Part Type: Reset IC; Status: RT-M7
U12 U13 = LDO_5P_FB: SMD IC PMIC;LDO-ADJ-300mA;SOT23-5; Manufacturer Part Number: Diodes;AP2127K-ADJTRG1; PN: 310030677; Part Type: LDO; Status: RT-M7
C23 C25 = CC: SMD CAP Ceramic 24pF-50V-5%-NPO;0402; Manufacturer Part Number: Yageo;CC0402JRNPO9BN240; PN: 302010825; Part Type: Ceramic; Rating: 50V,NPO; Status: RT-M7
C26 C27 = CC: SMD CAP Ceramic 4.7pF-50V-0.25pF-NPO;0402; Manufacturer Part Number: YAGEO;CC0402CRNPO9BN4R7; PN: 302010011; Part Type: Ceramic; Rating: 50V,NPO; Status: RT-M7
C17 C37 C49 C53 C55 C56 C61 C69 C72 C78 C88 C98 = CC: SMD CAP Ceramic 4.7uF-6.3V-20%-X5R;0402; Manufacturer Part Number: YAGEO;CC0402MRX5R5BB475; PN: 302010019; Part Type: Ceramic; Rating: 6.3V,X5R; Status: BeagleBone Carrier Board
C22 C66 = CC: SMD CAP Ceramic 100nF-16V-10%-X7R;0402; ASSY: DNP; Manufacturer Part Number: YAGEO;CC0402KRX7R7BB104; PN: 302010004; Part Type: Ceramic; Rating: 16V,X7R; Status: BeagleBone Carrier Board
J6 = Header_2+2P: SMD Male CONN HEADER 2P-1.25mm-卧贴; Manufacturer Part Number: 思拓展;1.25-2A-卧贴; PN: 320110900; Part Type: Header; Status: RT-M7
L2 = L: SMD Inductor 4.7uH-20%-1.1A;2520; Manufacturer Part Number: Samsung;CIG22L4R7MNE; PN: 303010149; Part Type: Inductor; Rating: 1.1A; Status: RT-M7
R20 = R: SMD RES 1.5K-5%-1/16W;0402; ASSY: DNP; Manufacturer Part Number: YAGEO;RC0402JR-071K5L; PN: 301010001; Part Type: RES; Rating: 5%; Status: BeagleBone Carrier Board
R21 R27 R48 = R: SMD RES 1.5K-5%-1/16W;0402; Manufacturer Part Number: YAGEO;RC0402JR-071K5L; PN: 301010001; Part Type: RES; Rating: 5%; Status: BeagleBone Carrier Board
R25 = R: SMD RES;2.2M-1%-1/16W-0402; Manufacturer Part Number: RC0402FR-072M2L; PN: 301010510; Part Type: RES; Rating: 1%; Status: RT-M7
R26 = R: SMD RES 1M-1%-1/16W;0402; ASSY: DNP; Manufacturer Part Number: YAGEO;RC0402FR-071ML; PN: 301010043; Part Type: RES; Rating: 1%; Status: BeagleBone Carrier Board
R31 R32 R49 R70 R91 = R: SMD RES 100K-5%-1/16W;0402; Manufacturer Part Number: YAGEO;RC0402JR-07100KL; PN: 301010033; Part Type: RES; Rating: 5%; Status: BeagleBone Carrier Board
R64 R73 R75 R77 R79 R81 R82 R85 R86 R93 = R: SMD RES 1K-5%-1/16W;0402; ASSY: DNP; Manufacturer Part Number: YAGEO;RC0402JR-071KL; PN: 301010006; Part Type: RES; Rating: 5%; Status: BeagleBone Carrier Board
R33-R35 R92 = R: SMD RES 100R-5%-1/16W;0402; Manufacturer Part Number: YAGEO;RC0402JR-07100RL; PN: 301010028; Part Type: RES; Rating: 5%; Status: BeagleBone Carrier Board
R103 = R: SMD RES 30K-1%-1/16W;0402; Manufacturer Part Number: YAGEO;RC0402FR-0730KL; PN: 301010048; Part Type: RES; Rating: 1%; Status: RT-M7
TP4 = T_POINT_R: TEST POINT PAD 40mil SMT, no part to order; AGILE_PN: 510-75618; CAD_APPROVED: Yes; HEIGHT: 0.1MM; ROHS: Yes
U8 = MIMXRT1052_BGA-196: SMD IC MCU;Cortex-M7;528MHz;MAPBGA-196(10*10mm); Manufacturer Part Number: NXP;MIMXRT1052CVL5B; PN: 310010999; Part Type: MCU; Status: RT-M7
U9 = MIC803: SMD IC PMIC;Reset Circuit;SC-70; Manufacturer Part Number: Microchip;MIC803-29D3VC3-TR; PN: 310031237; Part Type: Reset IC; Status: RT-M7
X1 = XTAL_2P: SMD Crystal 32.768KHz-12.5pF-20ppm-2P-3.2*1.5*0.9mm; Manufacturer Part Number: Epson;FC-135 32.7680KA-A3(指定品牌); PN: 306010138; Part Type: Crystal; Rating: 20ppm; Status: BeagleBone Carrier Board
X2 = XTAL_4P: SMD Crystal;24MHz-9pF-10ppm-2.5*3.2*0.6mm; Manufacturer Part Number: Epson Timing;TSX-3225 24.0000MF20G-AC3; PN: 306010101; Part Type: Crystal; Rating: 10ppm; Status: RT-M7
C44 C116 = CC: SMD CAP Ceramic 18pF-50V-5%-NPO;0402; ASSY: DNP; Manufacturer Part Number: YAGEO;CC0402JRNPO9BN180; PN: 302010016; Part Type: Ceramic; Rating: 50V,NPO; Status: BeagleBone Carrier Board
D4 D7-D10 D12 D13 = DIODE_TVS_BI-DIR: SMD Diode ESD 0.05pF;0402; Manufacturer Part Number: SEMITEL;ESDPSA0402V05; PN: 304060074; Part Type: TVS; Rating: 5V; Status: BeagleBone Carrier Board
FB1-FB3 FB5-FB8 = FB: SMD Ferrite Bead;120R-2A;0603; Manufacturer Part Number: Murata;BLM18PG121SN1D; PN: 303030024; Part Type: Ferrite Bead; Rating: 2A; Status: BeagleBone Carrier Board
J7 = MicroSD_Card_8P: SMD Micro SD Card Holder;8P-13.9*15mm; Manufacturer Part Number: ALPS;SCHA5B0200; PN: 320090010; Part Type: SD Card; Status: BeagleBone Carrier Board
R15 R38 R43 R44 R47 R56 R58 R60 R63 R66 R69 R96 = R: SMD RES 33R-5%-1/16W;0402; Manufacturer Part Number: YAGEO;RC0402JR-0733RL; PN: 301010034; Part Type: RES; Rating: 5%; Status: BeagleBone Carrier Board
R3 R62 R135 = R: SMD RES 10K-5%-1/16W;0402; ASSY: DNP; Manufacturer Part Number: YAGEO;RC0402JR-0710KL; PN: 301010004; Part Type: RES; Rating: 5%; Status: BeagleBone Carrier Board
U4 = SDRAM_BGA54: SMD IC Memory;SDRAM;4M*16*4 banks;VFBGA-54 (8*8mm); Manufacturer Part Number: ISSI;IS42S16160J-6BLI; PN: 310090807; Part Type: SDRAM; Status: RT-M7
U7 = HyperFlash_FBGA-24: SMD IC Memory;HyperFlash;512Mb;1.8V;FBGA-24; ASSY: DNP; Manufacturer Part Number: Cypress Semiconductor;S26KS512SDPBHI02; PN: 310090810; Part Type: HyperFlash; Status: RT-M7
U11 = QPI_8P: SMD IC Memory;QPI Flash;64Mb;1.8V;SOIC-8; Manufacturer Part Number: ISSI;IS25WP064A-JBLE; PN: 310090808; Part Type: QPI; Status: RT-M7
C33-C35 = CC: SMD CAP Ceramic 1uF-10V-10%-X5R;0402; ASSY: DNP; Manufacturer Part Number: YAGEO;CC0402KRX5R6BB105; PN: 302010040; Part Type: Ceramic; Rating: 10V,X5R; Status: BeagleBone Carrier Board
C36 = CC: SMD CAP Ceramic 10pF-50V-5%-NPO;0402; ASSY: DNP; Manufacturer Part Number: YAGEO;CC0402JRNPO9BN100; PN: 302010001; Part Type: Ceramic; Rating: 50V,NPO; Status: BeagleBone Carrier Board
FB4 = FB: SMD Ferrite Bead;120R-2A;0603; ASSY: DNP; Manufacturer Part Number: Murata;BLM18PG121SN1D; PN: 303030024; Part Type: Ferrite Bead; Rating: 2A; Status: BeagleBone Carrier Board
J5 = FPC50_For_Emb: SMD FPC CONN;50P-0.5-L29.4*W6.1*H2.0mm; Manufacturer Part Number: 文章济美科技;AFC01-S50F1A-00; PN: 320060344; Part Type: FPC; Status: Arch Mix
LED2 = RGB_LED: SMD LED RGB;4P-L3.5*W2.8*H1.9mm; Manufacturer Part Number: 国星光电;FM-3528RGBA-HF; PN: 304090952; Part Type: LED; Status: RT-M7
Q1 = PMOS_123: SMD MOSFET P-CH 20V-3.6A;SOT-23; Manufacturer Part Number: Diodes Incorporated;DMP2035U-7; PN: 305030683; Part Type: PMOS; Rating: 20V 3.6A; Status: IOT Enabling Dongle Board
R19 R76 R88 R90 = R: SMD RES 10K-5%-1/16W;0402; Manufacturer Part Number: YAGEO;RC0402JR-0710KL; PN: 301010004; Part Type: RES; Rating: 5%; SIGNAL_MODEL: RES_0402_CC_DISCRETE_0.45_MM_47_0; Status: BeagleBone Carrier Board
R29 R50 R52 = R: SMD RES 4.7K-5%-1/16W;0402; Manufacturer Part Number: YAGEO;RC0402JR-074K7L; PN: 301010010; Part Type: RES; Rating: 5%; Status: BeagleBone Carrier Board
R36 = R: SMD RES 100R-5%-1/16W;0402; ASSY: DNP; Manufacturer Part Number: YAGEO;RC0402JR-07100RL; PN: 301010028; Part Type: RES; Rating: 5%; Status: BeagleBone Carrier Board
R89 = R: SMD RES 1K-5%-1/16W;0402; ASSY: DNP; Manufacturer Part Number: YAGEO;RC0402JR-071KL; PN: 301010006; Part Type: RES; Rating: 5%; SIGNAL_MODEL: RES_0402_CC_DISCRETE_0.45_MM_47_0; Status: BeagleBone Carrier Board
SW1 = DIP_Switches_4CH: SMD Top DIP Switches;2*4P-L6.21*W6.20*H2.3mm; Manufacturer Part Number: Otax;KHS42-E; PN: 311080206; Status: RT-M7
SW2-SW4 = Tactile_Switch_4P: SMD Top Button 1.57N;4P-L4.6*W3.2*H2.5mm; Manufacturer Part Number: ALPS;SKRPABE010; PN: 311020518; Status: BeagleBone Carrier Board
C1 C111 = CC: SMD CAP Ceramic 22uF-16V-10%-X7R;1206; Manufacturer Part Number: Yageo;CC1206KKX7R7BB226; PN: 302010182; Part Type: Ceramic; Rating: 16V,X7R; Status: BeagleBone Carrier Board
J1 J2 = MicroUSB_5+6P: SMD Micro USB Type B;(5P+4)-7.8*5.06mm; Manufacturer Part Number: 百斯特;USB-MC-001-05; PN: 320010050; Part Type: USB; Status: BeagleBone Carrier Board
J3 J4 = Header_1x22: DIP Black Male Header VERT;1*22P-2.54-2.54-11.6/3.0mm; Manufacturer Part Number: 思拓展;; PN: 320020838; Part Type: Header; Status: RT-M7
L3 L4 = CL: SMD Common Mode Filter 90R-400mA;4P-L2.0*W1.2*H1.4m; Manufacturer Part Number: Bourns;SRF2012-900YA; PN: 303050063; Part Type: Common Mode Filter; Rating: 400mA; Status: BeagleBone Carrier Board
Q2 = NMOS_123: SMD MOSFET N-CH 50V-200mA;SOT-323-3; Manufacturer Part Number: Diodes Inc;BSS138W-7-F; PN: 305030000; Part Type: NMOS; Rating: 50V 200mA; Status: BeagleBone Carrier Board
R4 = R: SMD RES 0R-5%-1/16W;0402; ASSY: DNP; Manufacturer Part Number: YAGEO;RC0402JR-070RL; PN: 301010000; Part Type: RES; Rating: 5%; SIGNAL_MODEL: RES_0402_CC_DISCRETE_0.45_MM_47_0; Status: BeagleBone Carrier Board
U1 = MIC2026: SMD IC PMIC;SWITCH-2CH;SOIC-8; Manufacturer Part Number: Microchip;MIC2026-1YM-TR; PN: 310031315; Part Type: Power Switch; Status: BeagleBone Carrier Board
U2 U3 = TPD4S012: SMD Diode TVS;4-Ch USB ESD Solution with-SON-6（1.45x1）; Manufacturer Part Number: Texas Instruments;TPD4S012DRYR; PN: 304050020; Part Type: ESD; Status: BeagleBone Carrier Board
U10 = SN74LVC2G241: SMD IC Logic;US8(8-VFSOP; Manufacturer Part Number: TI;SN74LVC2G241DCUR; PN: 310050078; Part Type: Buffer; Status: BeagleBone Carrier Board

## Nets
3V3_LCD: C41.1 FB4.2 J5.45(VDD1_3V3) J5.46(VDD2_3V3) Q1.3(D)
3V3_SD: C42.1 C43.1 FB5.2 J7.4(VDD) R37.1 R57.1 R59.1 R61.1 R62.1 R65.1 R68.1
5V_HOST: C2.1 FB1.2 J1.1(VBUS) U2.6(VBUS)
5V_LCD: C40.1 FB3.2 J5.47(VDD3_5V) J5.48(VDD4_5V)
5V_OTG: C3.1 C5.1 C99.1 FB2.2 J2.1(VBUS) J3.3 J4.3 U3.6(VBUS)
5V_USB_HOST: C21.1 C111.1 C112.1 FB1.1 U1.8(OUTA) U8.P6(USB_OTG2_VBUS)
5V_USB_OTG: C1.1 C38.1 C68.1 C108.1 C109.1 C113.1 C114.1 FB2.1 FB3.1 R5.2 R8.1 U1.7(IN) U8.N6(USB_OTG1_VBUS) U13.1(IN) U13.3(~{SHDN})
GND: C1.2 C2.2 C3.2 C4.2 C5.2 C6.2 C7.2 C8.2 C9.2 C10.2 C11.2 C12.2 C13.2 C14.2 C15.2 C17.2 C18.2 C19.2 C20.2 C21.2 C22.2 C23.2 C24.2 C25.2 C26.2 C27.2 C28.2 C29.2 C30.2 C31.2 C32.2 C33.2 C34.2 C35.2 C36.2 C37.2 C38.2 C39.2 C40.2 C41.2 C42.2 C43.2 C44.2 C45.2 C46.2 C47.2 C48.2 C49.2 C50.2 C51.2 C52.2 C53.2 C54.2 C55.2 C56.2 C57.2 C58.2 C59.2 C60.2 C61.2 C62.2 C63.2 C64.2 C65.2 C66.2 C67.2 C68.2 C69.2 C70.2 C71.2 C72.2 C73.2 C74.2 C75.2 C76.2 C77.2 C78.2 C79.2 C80.2 C81.2 C82.2 C83.2 C84.2 C85.2 C86.2 C87.2 C88.2 C89.2 C90.2 C91.2 C93.2 C94.2 C95.2 C96.2 C97.2 C98.2 C99.2 C100.2 C101.2 C103.2 C104.2 C105.2 C106.2 C107.2 C108.2 C109.2 C110.2 C111.2 C112.2 C113.2 C114.2 C115.2 C116.2 D4.2 D7.2 D8.2 D9.2 D10.2 D12.2 D13.2 FB7.1 FB8.1 J3.2 J3.21 J4.2 J4.21 J5.1(B0) J5.2(B1) J5.3(B2) J5.9(GND1) J5.10(G0) J5.11(G1) J5.18(GND2) J5.19(R0) J5.20(R1) J5.21(R2) J5.27(GND3) J5.31(GND4) J5.33(GND5) J5.44(GND6) J6.2 J7.6(VSS) J7.9(GND) Q2.2(S) R1.1 R3.2 R9.2 R14.2 R16.1 R17.1 R18.1 R19.1 R25.2 R28.2 R32.2 R53.2 R67.2 R70.2 R74.1 R76.1 R78.1 R80.1 R83.1 R84.1 R87.1 R88.1 R90.1 R94.1 R119.2 R123.2 R125.2 R129.2 R135.2 R138.2 SW2.1(A1) SW2.3(A2) SW3.1(A1) SW3.3(A2) SW4.1(A1) SW4.3(A2) U1.6(GNG) U2.4(GND) U3.4(GND) U4.A1(VSS1) U4.A3(VSSQ1) U4.B7(VSSQ2) U4.C3(VSSQ3) U4.D7(VSSQ4) U4.E3(VSS2) U4.J1(VSS3) U5.4(PGND) U5.6(AGND) U6.1(GND) U7.B3(VSS) U7.B5(RFU2) U7.C1(VSSQ1) U7.C5(RFU3) U7.E5(VSSQ2) U8.A1(VSS1) U8.A14(VSS2) U8.B5(VSS3) U8.B10(VSS4) U8.E2(VSS5) U8.E13(VSS6) U8.G7(VSS7) U8.G8(VSS8) U8.H7(VSS9) U8.H8(VSS10) U8.J7(VSS11) U8.J8(VSS12) U8.K2(VSS13) U8.K6(TEST_MODE) U8.K9(NGND_KEL0) U8.K13(VSS14) U8.L9(VSS15) U8.N1(DCDC_GND_1) U8.N2(DCDC_GND_2) U8.N5(VSS16) U8.N8(VSS17) U8.P1(VSS18) U8.P14(VSS19) U9.1(GND) U10.1(~{1OE}) U10.4(GND) U11.4(GND) U12.2(GND) U13.2(GND) X2.2 X2.4
GND_EARTH: C115.1 J1.8(SHLD3) J1.9(SHLD4) J1.10(SHLD5) J1.11(SHLD6) J2.8(SHLD3) J2.9(SHLD4) J2.10(SHLD5) J2.11(SHLD6) J5.51(GND7) J5.52(GND8) J6.3 J6.4 J7.13(GND3) J7.14(GND4) MTG1.1(TP) MTG2.1(TP) MTG3.1(TP) MTG4.1(TP) R138.1
VDD_COIN_3V: D11.1(A) J3.18 J6.1 R64.1 TP4.1(TP)
VDD_HIGH_IN_3V3: C49.1 C50.1 C51.1 R71.2 R72.2 U8.P12(VDD_HIGH_IN)
VDD_SNVS_3V3: C11.1 C103.1 D3.1(A) R20.1 R128.2 R130.2 U6.4(VCC)
VDD_SNVS_CAP: C54.1 C55.1 U8.M10(VDD_SNVS_CAP)
VDD_SNVS_IN: C60.1 R31.1 R91.1 R92.2 U8.M9(VDD_SNVS_IN)
VDD_SOC_IN: C57.1 C58.1 C63.1 C65.1 C69.1 C75.1 C76.1 C77.1 C79.1 C81.1 C82.1 R107.1 U8.F6(VDD_SOC_IN_1) U8.F7(VDD_SOC_IN_2) U8.F8(VDD_SOC_IN_3) U8.F9(VDD_SOC_IN_4) U8.G6(VDD_SOC_IN_5) U8.G9(VDD_SOC_IN_6) U8.H6(VDD_SOC_IN_7) U8.H9(VDD_SOC_IN_8) U8.J5(DCDC_SENSE) U8.J9(VDD_SOC_IN_9)
VDD_USB_3V: C48.1 C59.1 U8.K8(VDD_USB_CAP)
VDDA_1V1_CAP: C52.1 C53.1 U8.P10(NVCC_PLL)
VDDA_2V5_CAP: C61.1 C62.1 U8.P8(VDD_HIGH_CAP)
VDDA_ADC_3V3: C28.1 C29.1 C30.1 R30.2 U8.N14(VDDA_ADC_3P3)
BOOT_MODE[0]: R19.2 SW1.4(A4) U8.F11(GPIO_AD_B0_04)
BOOT_MODE[1]: R18.2 SW1.3(A3) U8.G14(GPIO_AD_B0_05)
CAN2_RX: J3.15 U8.L10(GPIO_AD_B0_15)
CAN2_TX: J3.14 U8.H14(GPIO_AD_B0_14)
DBG_Reset: J4.18 R51.2
DBG_SWD_3V3: D5.2(C) J4.22
DBG_SWD_CLK: J4.19 R43.2
DBG_SWD_DIO: J4.20 R44.2
DBG_UART1_3V3: D6.2(C) J3.22
DBG_UART1_RXD: J3.19 R70.1 U10.2(1A)
DBG_UART1_TXD: J3.20 U10.3(2Y)
DCDC_3V3: C4.1 C9.1 C10.1 C31.1 C32.1 C37.1 C39.1 C45.1 C46.1 C47.1 C56.1 C64.1 C94.1 C95.1 C105.1 D5.1(A) D6.1(A) FB4.1 FB5.1 FB6.1 J3.1 J4.1 L1.2 LED1.1(A) LED2.2(Anode) Q1.2(S) R2.1 R6.1 R7.1 R10.1 R21.1 R30.1 R39.1 R40.1 R41.1 R42.1 R45.1 R46.1 R49.1 R50.1 R52.1 R72.1 R73.1 R75.1 R77.1 R79.1 R81.1 R82.1 R85.1 R86.1 R89.1 R93.1 R97.1 R117.1 R121.1 R128.1 R133.1 R134.1 U5.5(OUT) U8.E6(NVCC_EMC_1) U8.E9(NVCC_GPIO_1) U8.F5(NVCC_EMC_2) U8.F10(NVCC_GPIO_2) U8.J10(NVCC_GPIO_3) U10.7(2OE) U10.8(VCC) U12.1(IN) U12.3(~{SHDN})
DCDC_OUT: C19.1 C20.1 C84.1 L2.2 R107.2
ENET_CRS_DV: J3.5 U8.C12(GPIO_B1_06)
ENET_MDC: J3.7 U8.A7(GPIO_EMC_40)
ENET_MDIO: J3.6 U8.C7(GPIO_EMC_41)
ENET_RXD0: J3.9 U8.E12(GPIO_B1_04)
ENET_RXD1: J3.8 U8.D12(GPIO_B1_05)
ENET_RXER: J3.4 U8.C13(GPIO_B1_11)
ENET_TX_CLK: J3.13 U8.B13(GPIO_B1_10)
ENET_TXD0: J3.11 U8.B12(GPIO_B1_07)
ENET_TXD1: J3.10 U8.A12(GPIO_B1_08)
ENET_TXEN: J3.12 U8.A13(GPIO_B1_09)
Flash_RST: R101.1 U8.C14(GPIO_B1_14)
FLASH_VCC: C17.1 C18.1 C70.1 C73.1 C85.1 C87.1 C88.1 R23.1 R95.1 R99.1 R100.1 R102.1 R109.1 R117.2 R118.2 U7.B4(VCC) U7.D1(VCCQ1) U7.E4(VCCQ2) U8.K5(NVCC_SD1) U11.8(VCC)
FlexSPI_CLK: R96.1 R98.1 U8.L4(GPIO_SD_B1_07)
FlexSPI_CLK_B: U7.B1(~{CK}) U8.P2(GPIO_SD_B1_04)
FlexSPI_D0_A: R113.1 R114.2 U8.P3(GPIO_SD_B1_08)
FlexSPI_D0_B: U7.D5(DQ4) U8.M4(GPIO_SD_B1_03)
FlexSPI_D1_A: R112.1 R116.2 U8.N4(GPIO_SD_B1_09)
FlexSPI_D1_B: U7.E3(DQ5) U8.M3(GPIO_SD_B1_02)
FlexSPI_D2_A: R106.2 R108.1 U8.P4(GPIO_SD_B1_10)
FlexSPI_D2_B: U7.E2(DQ6) U8.M5(GPIO_SD_B1_01)
FlexSPI_D3_A: R111.1 R115.2 U8.P5(GPIO_SD_B1_11)
FlexSPI_D3_B: U7.E1(DQ7) U8.L5(GPIO_SD_B1_00)
FlexSPI_DQS: R110.1 U8.N3(GPIO_SD_B1_05)
FlexSPI_SS0: R104.1 R105.1 R109.2 U8.L3(GPIO_SD_B1_06)
GPIO_AD_B1_04: J4.4 U8.L12(GPIO_AD_B1_04)
GPIO_AD_B1_05: J4.5 U8.K12(GPIO_AD_B1_05)
GPIO_AD_B1_06: J4.6 U8.J12(GPIO_AD_B1_06)
GPIO_AD_B1_07: J4.7 U8.K10(GPIO_AD_B1_07)
GPIO_AD_B1_08: J4.8 U8.H13(GPIO_AD_B1_08)
HF_CLK: R98.2 U7.B2(CK)
HF_D0_A: R113.2 U7.D3(DQ0)
HF_D1_A: R112.2 U7.D2(DQ1)
HF_D2_A: R108.2 U7.C4(DQ2)
HF_D3_A: R111.2 U7.D4(DQ3)
HF_DQS: R110.2 U7.C3(RWDS)
HF_RST: R100.2 R101.2 U7.A4(~{RESET})
HF_SS0: R105.2 U7.C2(~{CS1})
I2C1_SCL: J3.16 J5.42(IIC_CLK) R50.2 U8.J11(GPIO_AD_B1_00)
I2C1_SDA: J3.17 J5.43(IIC_DAT) R52.2 U8.K11(GPIO_AD_B1_01)
LCD_BL_PWM: R4.1 R55.1 U8.M11(GPIO_AD_B0_02)
LCD_CLK: C36.1 J5.32(CLK) R47.2
LCD_PWREN: Q1.1(G) R67.1 U8.L7(PMIC_STBY_REQ)
LCDIF_CLK: R47.1 U8.D7(GPIO_B0_00)
LCDIF_D0: J5.4(B3) R79.2 R80.2 U8.C8(GPIO_B0_04)
LCDIF_D1: J5.5(B4) R86.2 R87.2 U8.B8(GPIO_B0_05)
LCDIF_D2: J5.6(B5) R82.2 R83.2 U8.A8(GPIO_B0_06)
LCDIF_D3: J5.7(B6) R77.2 R78.2 U8.A9(GPIO_B0_07)
LCDIF_D4: J5.8(B7) R75.2 R76.2 U8.B9(GPIO_B0_08)
LCDIF_D5: J5.12(G2) R89.2 R90.2 U8.C9(GPIO_B0_09)
LCDIF_D6: J5.13(G3) R16.2 SW1.1(A1) U8.D9(GPIO_B0_10)
LCDIF_D7: J5.14(G4) R73.2 R74.2 U8.A10(GPIO_B0_11)
LCDIF_D8: J5.15(G5) R85.2 R88.2 U8.C10(GPIO_B0_12)
LCDIF_D9: J5.16(G6) R17.2 SW1.2(A2) U8.D10(GPIO_B0_13)
LCDIF_D10: J5.17(G7) R93.2 R94.2 U8.E10(GPIO_B0_14)
LCDIF_D11: J5.22(R3) R81.2 R84.2 U8.E11(GPIO_B0_15)
LCDIF_D12: J5.23(R4) U8.A11(GPIO_B1_00)
LCDIF_D13: J5.24(R5) U8.B11(GPIO_B1_01)
LCDIF_D14: J5.25(R6) U8.C11(GPIO_B1_02)
LCDIF_D15: J5.26(R7) U8.D11(GPIO_B1_03)
LCDIF_ENABLE: J5.28(DEN) U8.E7(GPIO_B0_01)
LCDIF_HSYNC: J5.29(HSYNC) U8.E8(GPIO_B0_02)
LCDIF_VSYNC: J5.30(VSYNC) U8.D8(GPIO_B0_03)
LDO_1V8: C90.1 C91.1 C92.1 R118.1 R122.1 U12.5(OUT)
LDO_3V3: C102.1 C107.1 C110.1 R71.1 R120.1 R126.1 R130.1 U13.5(OUT)
MCU_DCDC_IN_3V3: C74.1 C78.1 C80.1 C83.1 C86.1 C89.1 R103.2 R119.1 R120.2 R121.2 U8.K4(DCDC_IN_Q) U8.L1(DCDC_IN_1) U8.L2(DCDC_IN_2)
MCU_ONOFF: C34.1 R34.2 U8.M6(ONOFF)
PMIC_ON_REQ: R11.1 R12.1 U8.K7(PMIC_ON_REQ)
POR_B: C66.1 R24.2 R36.2 R51.1 R54.1 R91.2 U8.M7(~{POR})
POR_BUTTON: C15.1 D1.2(C) R11.2 R35.2
PWR_USB_OTG: R5.1 U1.5(OUTB)
QF_CLK: R96.2 U11.6(SCK)
QF_D0_A: R114.1 U11.5(SI_IO0)
QF_D1_A: R116.1 U11.2(SO_IO1)
QF_D2_A: R23.2 R106.1 U11.3(~{WP}_IO2)
QF_D3_A: R95.2 R115.1 U11.7(~{HOLD}/~{RESET}_IO3)
QF_SS0: R104.2 U11.1(~{CE})
SAI1_MCLK: J4.9 U8.M13(GPIO_AD_B1_09)
SAI1_RX_BCLK: J4.11 U8.J13(GPIO_AD_B1_11)
SAI1_RX_SYNC: J4.10 U8.L13(GPIO_AD_B1_10)
SAI1_RXD/AD1_Y-: J4.12 J5.37(Y-) U8.H12(GPIO_AD_B1_12)
SAI1_TX_BCLK/AD3_X-: J4.14 J5.35(X-) U8.G12(GPIO_AD_B1_14)
SAI1_TX_SYNC/AD4_X+: J4.15 J5.34(X+) U8.J14(GPIO_AD_B1_15)
SAI1_TXD/AD2_Y+: J4.13 J5.36(Y+) U8.H11(GPIO_AD_B1_13)
SD1_CLK: C116.1 R63.1 U8.J3(GPIO_SD_B0_01)
SD1_CMD: R56.1 U8.J4(GPIO_SD_B0_00)
SD1_D0: R66.1 U8.J1(GPIO_SD_B0_02)
SD1_D1: R69.1 U8.K1(GPIO_SD_B0_03)
SD1_D2: R60.1 U8.H2(GPIO_SD_B0_04)
SD1_D3: R58.1 U8.J2(GPIO_SD_B0_05)
SD_CD: D4.1 J7.10(CD) R37.2 R38.2
SD_CD_SW: R38.1 U8.D13(GPIO_B1_12)
SD_CLK: C44.1 D10.1 J7.5(CLOCK) R62.2 R63.2
SD_CMD: D7.1 J7.3(CMD) R56.2 R57.2
SD_DAT0: D12.1 J7.7(DAT0) R65.2 R66.2
SD_DAT1: D13.1 J7.8(DAT1) R68.2 R69.2
SD_DAT2: D9.1 J7.1(DAT2) R60.2 R61.2
SD_DAT3: D8.1 J7.2(CD/DAT3) R58.2 R59.2
SDRAM_3V3: C13.1 C14.1 C93.1 C96.1 C97.1 C98.1 C100.1 C104.1 C106.1 FB6.2 R127.1 U4.A7(VDDQ1) U4.A9(VDD1) U4.B3(VDDQ2) U4.C7(VDDQ3) U4.D3(VDDQ4) U4.E7(VDD2) U4.J9(VDD3)
SDRAM_CLK: R15.2 U4.F2(CLK)
SEMC_A0: U4.H7(A0) U8.C2(GPIO_EMC_09)
SEMC_A1: U4.H8(A1) U8.G1(GPIO_EMC_10)
SEMC_A2: U4.J8(A2) U8.G3(GPIO_EMC_11)
SEMC_A3: U4.J7(A3) U8.H1(GPIO_EMC_12)
SEMC_A4: U4.J3(A4) U8.A6(GPIO_EMC_13)
SEMC_A5: U4.J2(A5) U8.B6(GPIO_EMC_14)
SEMC_A6: U4.H3(A6) U8.B1(GPIO_EMC_15)
SEMC_A7: U4.H2(A7) U8.A5(GPIO_EMC_16)
SEMC_A8: U4.H1(A8) U8.A4(GPIO_EMC_17)
SEMC_A9: U4.G3(A9) U8.B2(GPIO_EMC_18)
SEMC_A10: U4.H9(A10) U8.G2(GPIO_EMC_23)
SEMC_A11: U4.G2(A11) U8.B4(GPIO_EMC_19)
SEMC_A12: U4.G1(A12) U8.A3(GPIO_EMC_20)
SEMC_BA0: U4.G7(BA0) U8.C1(GPIO_EMC_21)
SEMC_BA1: U4.G8(BA1) U8.F1(GPIO_EMC_22)
SEMC_CAS: U4.F7(~{CAS}) U8.D3(GPIO_EMC_24)
SEMC_CKE: R129.1 U4.F3(CKE) U8.A2(GPIO_EMC_27)
SEMC_CLK: R15.1 U8.B3(GPIO_EMC_26)
SEMC_CS0: R127.2 U4.G9(~{CS}) U8.E1(GPIO_EMC_29)
SEMC_D0: U4.A8(DQ0) U8.E3(GPIO_EMC_00)
SEMC_D1: U4.B9(DQ1) U8.F3(GPIO_EMC_01)
SEMC_D2: U4.B8(DQ2) U8.F4(GPIO_EMC_02)
SEMC_D3: U4.C9(DQ3) U8.G4(GPIO_EMC_03)
SEMC_D4: U4.C8(DQ4) U8.F2(GPIO_EMC_04)
SEMC_D5: U4.D9(DQ5) U8.G5(GPIO_EMC_05)
SEMC_D6: U4.D8(DQ6) U8.H5(GPIO_EMC_06)
SEMC_D7: U4.E9(DQ7) U8.H4(GPIO_EMC_07)
SEMC_D8: U4.E1(DQ8) U8.C6(GPIO_EMC_30)
SEMC_D9: U4.D2(DQ9) U8.C5(GPIO_EMC_31)
SEMC_D10: U4.D1(DQ10) U8.D5(GPIO_EMC_32)
SEMC_D11: U4.C2(DQ11) U8.C4(GPIO_EMC_33)
SEMC_D12: U4.C1(DQ12) U8.D4(GPIO_EMC_34)
SEMC_D13: U4.B2(DQ13) U8.E5(GPIO_EMC_35)
SEMC_D14: U4.B1(DQ14) U8.C3(GPIO_EMC_36)
SEMC_D15: U4.A2(DQ15) U8.E4(GPIO_EMC_37)
SEMC_DM0: U4.E8(LDQM) U8.H3(GPIO_EMC_08)
SEMC_DM1: U4.F1(UDQM) U8.D6(GPIO_EMC_38)
SEMC_DQS: C22.1 U8.B7(GPIO_EMC_39)
SEMC_RAS: U4.F8(~{RAS}) U8.D2(GPIO_EMC_25)
SEMC_WE: U4.F9(~{WE}) U8.D1(GPIO_EMC_28)
SPDIF_IN: J4.17 U8.M12(GPIO_AD_B1_03)
SPDIF_OUT: J4.16 U8.L11(GPIO_AD_B1_02)
SWD_CLK: R32.1 R43.1 U8.F12(GPIO_AD_B0_07)
SWD_DIO: R44.1 R49.2 U8.E14(GPIO_AD_B0_06)
UART1_RXD: R46.2 U8.L14(GPIO_AD_B0_13) U10.6(1Y)
UART1_TXD: R45.2 U8.K14(GPIO_AD_B0_12) U10.5(2A)
USB1_GND: FB7.2 J2.5(GND)
USB2_GND: FB8.2 J1.5(GND)
USB_HOST_DN: J1.2(DM) L3.2 R131.2 U2.2(D-)
USB_HOST_DP: J1.3(DP) L3.3 R132.2 U2.1(D+)
USB_HOST_OC: R6.2 U1.2(FLGA) U8.M14(GPIO_AD_B0_00)
USB_HOST_PWR: R7.2 R135.1 U1.1(ENA) U8.B14(GPIO_B1_15)
USB_OTG1_DN: L4.1 R136.1 U8.M8(USB_OTG1_DN)
USB_OTG1_DP: L4.4 R137.1 U8.L8(USB_OTG1_DP)
USB_OTG1_ID: J2.4(ID) Q2.1(G) R134.2 U3.3(ID) U8.H10(GPIO_AD_B0_01)
USB_OTG1_OC: R133.2 U1.3(FLGB) U8.G11(GPIO_AD_B0_03)
USB_OTG2_DN: L3.1 R131.1 U8.N7(USB_OTG2_DN)
USB_OTG2_DP: L3.4 R132.1 U8.P7(USB_OTG2_DP)
USB_OTG_DN: J2.2(DM) L4.2 R136.2 U3.2(D-)
USB_OTG_DP: J2.3(DP) L4.3 R137.2 U3.1(D+)
USER_BUTTON: C33.1 R31.2 R33.2 U8.L6(WAKEUP)
USER_LED_B: R48.2 U8.G10(GPIO_AD_B0_11)
USER_LED_G: R29.2 U8.G13(GPIO_AD_B0_10)
USER_LED_R: R27.2 U8.F14(GPIO_AD_B0_09)
WDOG_B: C16.1 U8.D14(GPIO_B1_13)
N1426169: D3.2(C) D11.2(C) R64.2 R92.1
N1428044: C24.1 R20.2 R21.2 R22.1 U9.3(VCC)
N1428076: R22.2 R24.1 U9.2(~{RESET})
N1428666: C26.1 R25.1 R26.1 U8.P11(XTALI) X2.3
N1428682: L2.1 U8.M1(DCDC_LP_1) U8.M2(DCDC_LP_2)
N1428736: C27.1 R26.2 U8.N11(XTALO) X2.1
N1428810: C25.1 U8.N9(RTC_XTALI) X1.1
N1428818: C71.1 R103.1 U8.K3(DCDC_PSWITCH)
N1428874: C23.1 U8.P9(RTC_XTALO) X1.2
N1430764: C6.1 C7.1 C8.1 R8.2 R124.1 U5.2(VIN)
N1430772: L1.1 U5.3(SW)
N1431030: R9.1 R10.2 U5.7(FB)
N1431040: C12.1 R12.2 R13.2 R124.2 U5.8(EN) U6.2(~{RESET})
N1431138: C101.1 TP3.1(TP) U5.1(PG)
N1431606: C16.2 D2.2(C) R14.1
N1435220: C67.1 C72.1 R97.2 U8.J6(NVCC_SD0)
N1441990: TP1.1(TP) U8.N12(~{USB_OTG1_CHD})
N1446802: R102.2 U7.A5(~{INT})
N1446884: R99.2 U7.A2(~{RSTO})
N1454429: Q2.3(D) R2.2 R3.1 R4.2 U1.4(ENB)
N1538445: R39.2 SW1.8(B1)
N1538449: R40.2 SW1.7(B2)
N1538453: R41.2 SW1.6(B3)
N1538457: R42.2 SW1.5(B4)
N1582760: R34.1 SW4.2(B1) SW4.4(B2)
N1582904: C35.1 R35.1 R36.1 SW3.2(B1) SW3.4(B2)
N1658417: R33.1 SW2.2(B1) SW2.4(B2)
N1660774: R28.1 U8.F13(GPIO_AD_B0_08)
N1700883: LED1.2(C) R1.2
N1720722: LED2.1(Red) R27.1
N1720728: LED2.3(Blue) R48.1
N1720734: LED2.4(Green) R29.1
N1744694: J5.49(RESET) R54.2
N1744704: J5.50(PWREN) R53.1 R55.2
N1790471: D1.1(A) D2.1(A) R13.1 U6.3(~{MR})
N1791257: TP2.1(TP) U8.N10(GPANAIO)
N1827694: C102.2 R125.1 R126.2 U13.4(FB)
N1830761: C92.2 R122.2 R123.1 U12.4(FB)

Not connected (* = marked no-connect by the designer): J1 4(ID)* 6(SHLD1)* 7(SHLD2)*; J2 6(SHLD1)* 7(SHLD2)*; J5 38(SPI_CLK) 39(SPI_MOSI) 40(SPI_MISO) 41(SPI_CS); J7 11(GND1)* 12(GND2)* 15(GND5)* 16(GND6)*; U2 3(ID)* 5(NC)*; U3 5(NC)*; U4 E2(NC)*; U7 A3(RFU1)*; U8 N13(CCM_CLK1_P)* P13(CCM_CLK1_N)*

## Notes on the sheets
sheet 1
- Up to 25 mA
- VALUE TBD
- Up to 25 mA
- MCU PINOUT
- By Default
- Not Connected
- JTAG_TMS
- JTAG_TCK
- JTAG_MOD
- JTAG_TDI
- JTAG_TDO
- JTAG_nTRST
- AUD_INT
sheet 2
- VDDHIGH / NVCC_xxx
- Current 2A
  I_Quiescent : 40μA
- 5V
- Layout Note:
- Add Silkscreen:
- LED1: POWER
- Vfb=0.6V
- # R36/R39 = 4.5
- # PG pin is pulled up to
  VIN by the internal
  resistor 500K OHM
- SNVS
- ADC
- # GPIO/WDOG PWR OFF->ON
- 3V3 LDO
- MAX 300 mA
- 3V3 LDO for SNVS
- DCDC_IN
- VDD_HIGH_IN
- FLASH VCC
- 1V8 LDO
- MAX 300 mA
- FLASH VCC
sheet 3
- Up to 34.5mA
- 1.1V
- Max loading = 500mA
- Up to 75mA
- Layout Note:
- Add Silkscreen:
- Pin1: 3V
- Up to 1mA
- Pin2: GND
- # Open Drain
- Up to 300 mA
- 1.1V
- FOR OSC STARTUP
- Max loading = 500mA
- PSWITCH RC Delay
sheet 4
- #####  Arch Mix Blcok Diagram  #####
- 2.54MM 1x22Pin Expansion PIN Header J3
- RMII x1 , CAN x1 , I2C x1 , UART x1 , RTC BAT x1 , 5V x1 , 3V3 x2 , GND x2
- RMII
- CAN
- I2C
- UART
- RTC BAT
- SDRAM
- USB OTG
- USB OTG1
- x16 bits
- 32MB
- USB HOST
- USB OTG2
- HyperFlash
- 64MB
- FlexSPI
- NXP
- QSPI Flash
- 8MB
- Switches
- i.MX RT1050
- x1 ONOFF
- IOs
- x1 Reset
- SD0
- SD SLOT
- ARM Cortex - M7
- x1 User
- T-Flash
- DIP
  Switches
- LCD
- BOOT CFG
- DISP
- RGB TFT
- RTC BAT
  Connector
- RTC BAT
- x3 GPIOs
- LED
- RGB LED
- CSI
- I2S
- ADC
- SPDIF
- POR
- SWD
- 2.54MM 1x22Pin Expansion PIN Header J4
- CSI x1 , I2S x1 , ADC x4 , SPDIF IN/OUT x1 , POR x1 , SWD x1 , 5V x1 , 3V3 x2 , GND x2
sheet 5
- MAX 150 mA @3.3V
- MicroSD CARD
- Review Note:
- FOR SD BOOT, ROM NEED SD_CD_SW PIN KEPT LOW:
- CARD INSERT
  Pin10_CD Connected to Pin9_GND --> SD_CD_SW=LOW
- CARD OFF
  Pin10_CD Float --> SD_CD_SW=HIGH
- Layout Note:
- Place R15 Close To MCU.
- SDRAM 32MB
- Layout Note:
- Layout Note:
- Place RC C116 R63 C44 Close To MCU.
- The SDRAM interface (running at up to 166 MHz):
- 1. The SDRAM routing must be separated into three groups: data, address, and control.
- 2. Route all signals at the same length within 100 Mils.
- 3. The controlled impedance for the single-ended traces must be 50 Ω.
- The SD module interfaces (running at up to 50 MHz):
- Option 1: USE HyperFlash (DNP U11 and series R)
- 1. Follow similar SDRAM rules for data, address, and control as for the SD interfaces.
- Option 2: USE QSPI FLASH (DNP U7 and series R)
- 1V8 QSPI Flash 8MB
- 1V8 HyperFlash 64MB
- MAX 180 mA @1.8V
- Layout Note:
- The FlexSPI interface (HyperFlash, QSPI Flash, running at up to 166 MHz):
- 1. Follow similar SDRAM rules for data, address, and control as for the FlexSPI interfaces.
- 2. 有分叉的信号，走"T"型拓扑结构，即分叉电阻按"T"型放置，且两个电阻放到一起，确保尾巴尽量短。
- BOM Note:
- 3. 需放到一起的电阻包括：R105 and R104, R98 and R96, R113 and R114, R112 and R116, R108 and R106, R111 and R115。
- 4. 以下信号组，需要控制等长：
- Flash_RST is 3.3V IO, DNP R101 when
  the power supply voltages of HyperFlash U7 is 1.8V.
- FlexSPI_SS0 + HF_SS0 ,
  FlexSPI_CLK + HF_CLK,
  FlexSPI_D0_A + HF_D0_A,
  FlexSPI_D1_A + HF_D1_A,
  FlexSPI_D2_A + HF_D2_A,
  FlexSPI_D3_A + HF_D3_A.
  FlexSPI_DQS + HF_DQS,
  FlexSPI_CLK_B,
  FlexSPI_D0_B,
  FlexSPI_D1_B,
  FlexSPI_D2_B,
  FlexSPI_D3_B
- FlexSPI_SS0 + QF_SS0 ,
  FlexSPI_CLK + QF_CLK,
  FlexSPI_D0_A + QF_D0_A,
  FlexSPI_D1_A + QF_D1_A,
  FlexSPI_D2_A + QF_D2_A,
  FlexSPI_D3_A + QF_D3_A.
sheet 6
- USB Power Switch
- USB OTG
- EN=ACTIVE HIGH
- Layout Note:
- Debug Interface
- The USB interface (USB 2.0):
- UART
- SWD
- 1. Route the high-speed clocks and the DP and DM differential pair firstly.
- 2. Route the DP and DM signals on the top (or bottom) layer of the board.
- 3. The trace width and spacing of the DP and DM signals must
       meet the differential impedance requirement of 90 Ω.
- USB HOST
- 4. Match the overall differential length difference to less than 5 mils.
- Layout Note:
- Layout Note:
- 5. Keep the DP and DM traces as short as possible.
- Add Silkscreen:
- Add Silkscreen:
- J3: UART
- Pin22: 3V3
- J4: SWD
- Pin22: 3V3
- Pin21: GND
- Pin21: GND
- Pin20: TXD
- Pin20: SWDIO
- Pin19: RXD
- Pin19: SWDCLK
- Pin18: RESET
- Expansion Headers
- CSI_PIXCLK
- CSI_MCLK
- CSI_VSYNC
- CSI_HSYNC
- CSI_D8
- CSI_D9
- CSI_D7
- CSI_D6
- Debug UART
- CSI_D5
- CSI_D4
- CSI_D3
- CSI_D2
- Layout Note:
- Layout Note:
- The ENET(RMII) signals must be length-matched by TX and RX groups:
  That is, the TX group should be matched within 300 Mil (7.62 mm),
  and the RX group should be matched within 300 Mil (7.62 mm).
  Total length should not exceed 1750 Mil (44.5 mm).
  There is no requirement to match the TX and RX groups because their clocks are not related.
- The CSI interface (running at up to 80 MHz):
- 1. Route all signals at the same length within 100 Mils.
- 2. The controlled impedance for the single-ended traces must be 50 Ω.
sheet 7
- Schematic: Arch Mix
- Revision History
- SHEET
- SHEET NAME
- DATE
- REVISION
- DESCRIPTION
- 01
- Title / Revision History
- 2018/11/20
- Arch Mix_v1.0_SCH_181120
- Initial Release
- 02
- Block Diagram
- 03
- Main Power
- 04
- MCU Power
- 05
- MCU PinOut
- 06
- SDRAM / Flash / SD Card
- 07
- Boot CFG / LCD / LED / BUT
- 08
- USB / EXP Headers
sheet 8
- FUSE MAP
- 0/1
- 0/1
- 0/1
- 0/1
- 0/1
- 0/1
- 0/1
- 0/1
- 0/1
- 0/1
- 0/1
- 0/1
- TYPE
- BOOT_CFG[11]
- BOOT_CFG[10]
- BOOT_CFG[9]
- BOOT_CFG[8]
- BOOT_CFG[7]
- BOOT_CFG[6]
- BOOT_CFG[5]
- BOOT_CFG[4]
- BOOT_CFG[3]
- BOOT_CFG[2]
- BOOT_CFG[1]
- BOOT_CFG[0]
- FLASH_TYPE
  000-Device supports 3B read by default
  001-Device supports 4B read by default
  010-HyperFlash 1V8
  011-HyperFlash 3V3
  100-MXIC Octal DDR
- HOLD TIME:
  00 - 500us
  01 - 1ms
  10 - 3ms
  11 - 10ms
- Infinit-Loop:
  (Debug USE only)
  0 - Disable
  1- Enable
- EncryptedXIP
  0 - Disabled
  1- Enabled
- FlexSPI1
  (Serial NOR)
- 0
- 0
- 0
- 0
- Reserved
- SD Power
  Cycle Enable:
  '0' - No power
  cycle
  '1' - Enabled via
  USDHC_RST pad
- SD Loopback
  Clock Source Sel:
  (for SDR50 and
  SDR104 only)
  '0' - through SD
  '1' -  direct
- SD/SDXC Speed:
  00 - Normal/SDR12
  01 - High/SDR25
  10 - SDR50
  11 - SDR104
- Infinit-Loop:
  (Debug USE only)
  0 - Disable
  1- Enable
- Bus Width:
  0 - 1-bit
  1 - 4-bit
- SD1 VOLTAGE
  SELECTION:
  0 - 3.3V
  1 - 1.8V
- Port Select:
  0 - eSDHC1
  1 - eSDHC2
- Fast Boot:
  0 - Regular
  1 - Fast Boot
- SD
- Reserved
- 0
- 1
- Button
- LCD Interface
- RGB LED
- MCU ONOFF
- RESET
- USER_BUT
- BOOT Configuration
- Layout Note:
- The LCD interface (running at up to 75 MHz):
- NOTE: SWitches: OFF --> 0; ON --> 1
- 1. Route all signals at the same length within 100 Mils.
- DEVICE
- BOOT_CFG
- SW1
- 2. The controlled impedance for the single-ended traces must be 50 Ω.
- HyperFlash
- 0x02_00
- 0 , 1 , 1 , 0
- QSPI Flash
- 0x00_00
- 0 , 0 , 1 , 0
- SD
- 0x00_40
- 1 , 0 , 1 , 0
- V_IO=3.3V
- BT_CFG[0]
- GPIO_B0_04
- BT_CFG[1]
- GPIO_B0_05
- BT_CFG[2]
- BT_CFG[3]
- GPIO_B0_06
- GPIO_B0_07
- BT_CFG[4]
- GPIO_B0_08
- BT_CFG[5]
- GPIO_B0_09
- BT_CFG[6]
- GPIO_B0_10
- BT_CFG[7]
- GPIO_B0_11
- BT_CFG[8]
- GPIO_B0_12
- BT_CFG[9]
- GPIO_B0_13
- BT_CFG[10]
- GPIO_B0_14
- BT_CFG[11]
- GPIO_B0_15
- BOOT_MODE[0]
- GPIO_AD_B0_04
- BOOT_MODE[1]
- GPIO_AD_B0_05
